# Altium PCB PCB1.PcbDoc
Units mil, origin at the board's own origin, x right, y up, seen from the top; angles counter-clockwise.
Board outline 1411.86 x 1442.8 mil, 4 copper layers (Top Layer, GND, Sign, Bottom Layer), stack 74.06 mil thick; 76 components, 64 nets, 335 pads, 393 vias.
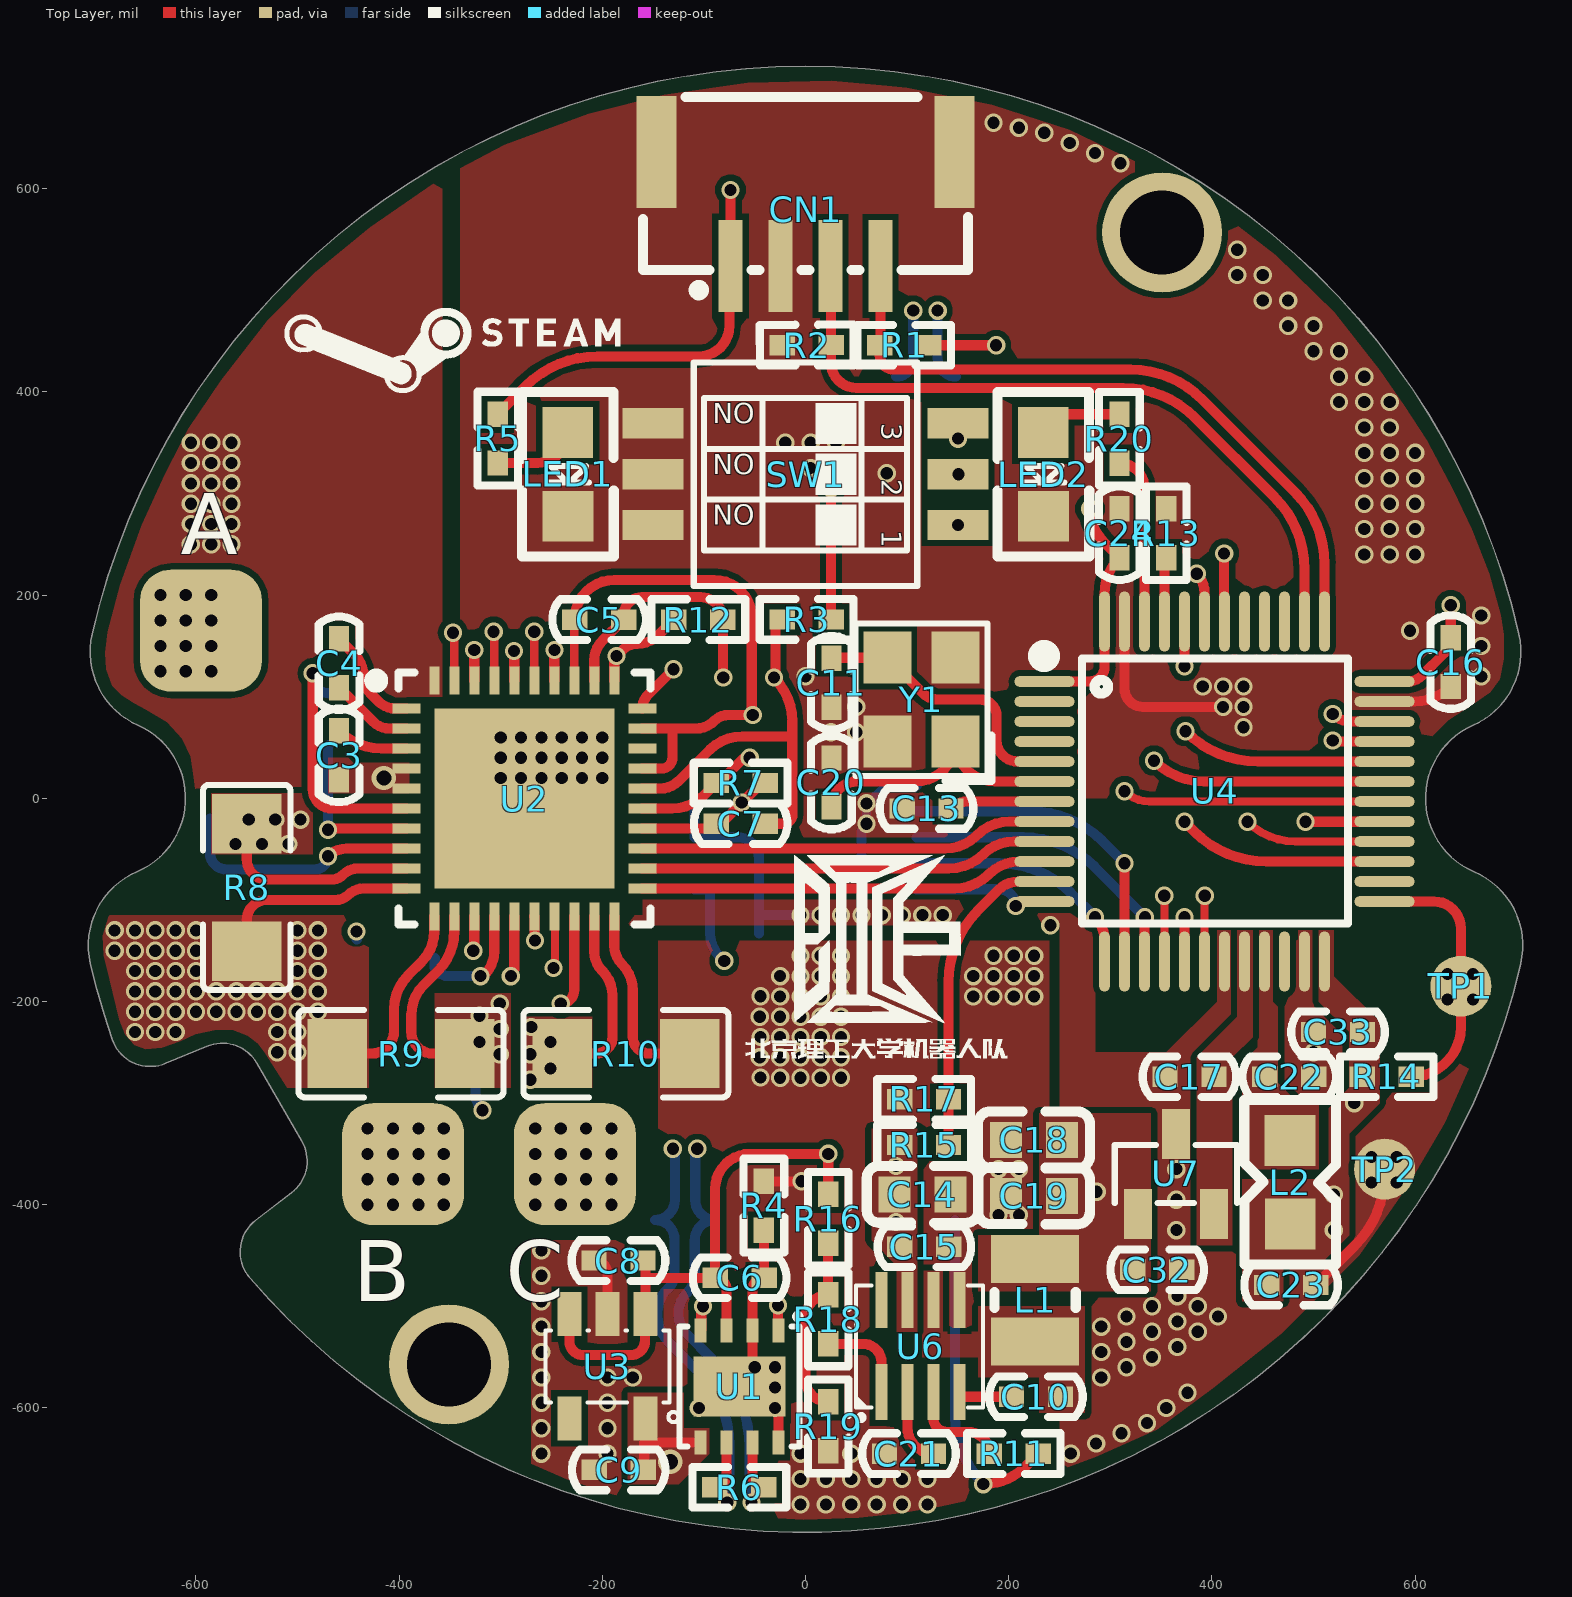
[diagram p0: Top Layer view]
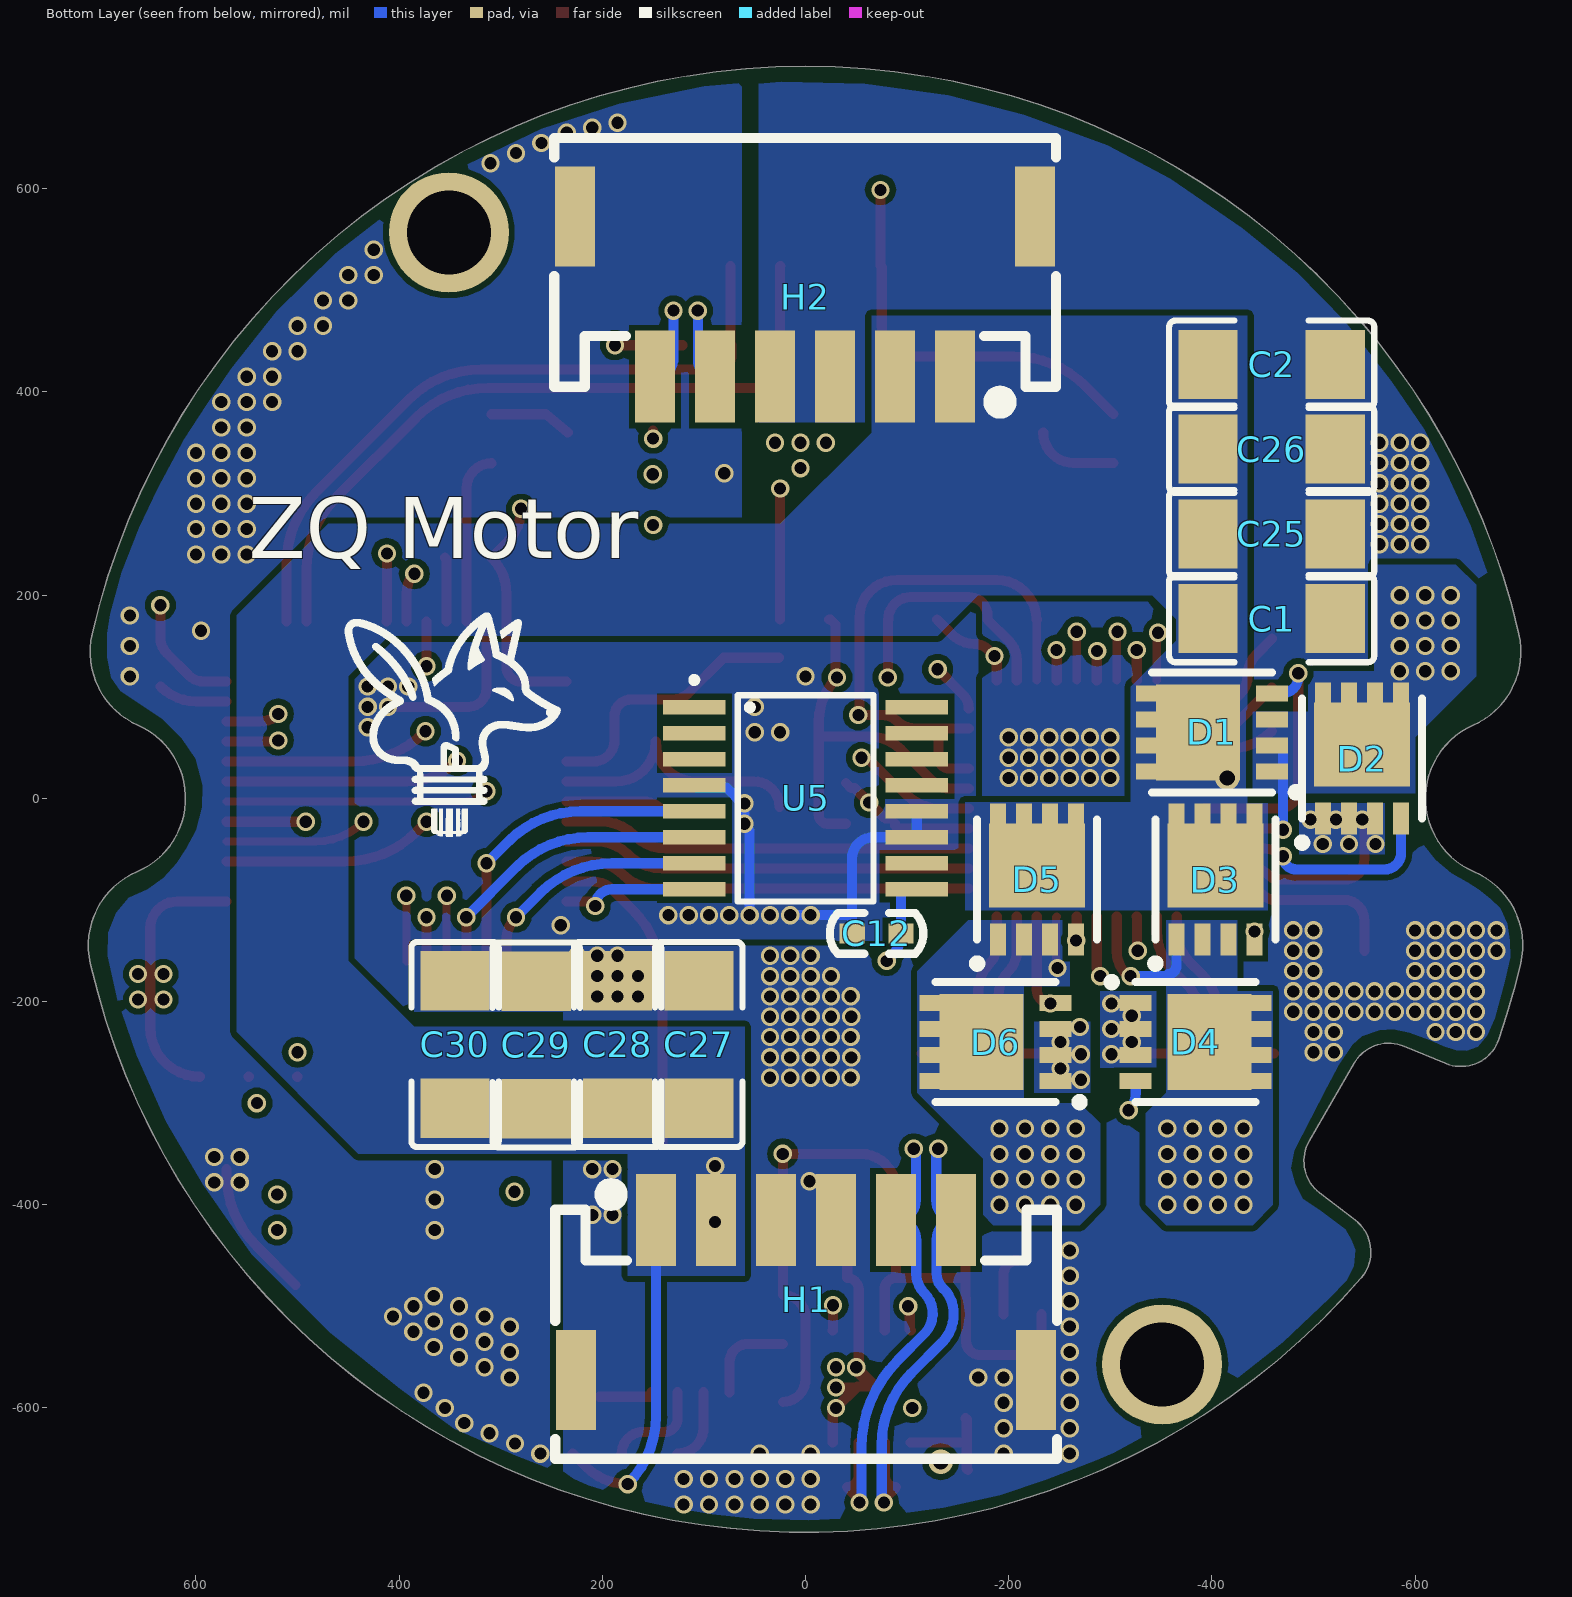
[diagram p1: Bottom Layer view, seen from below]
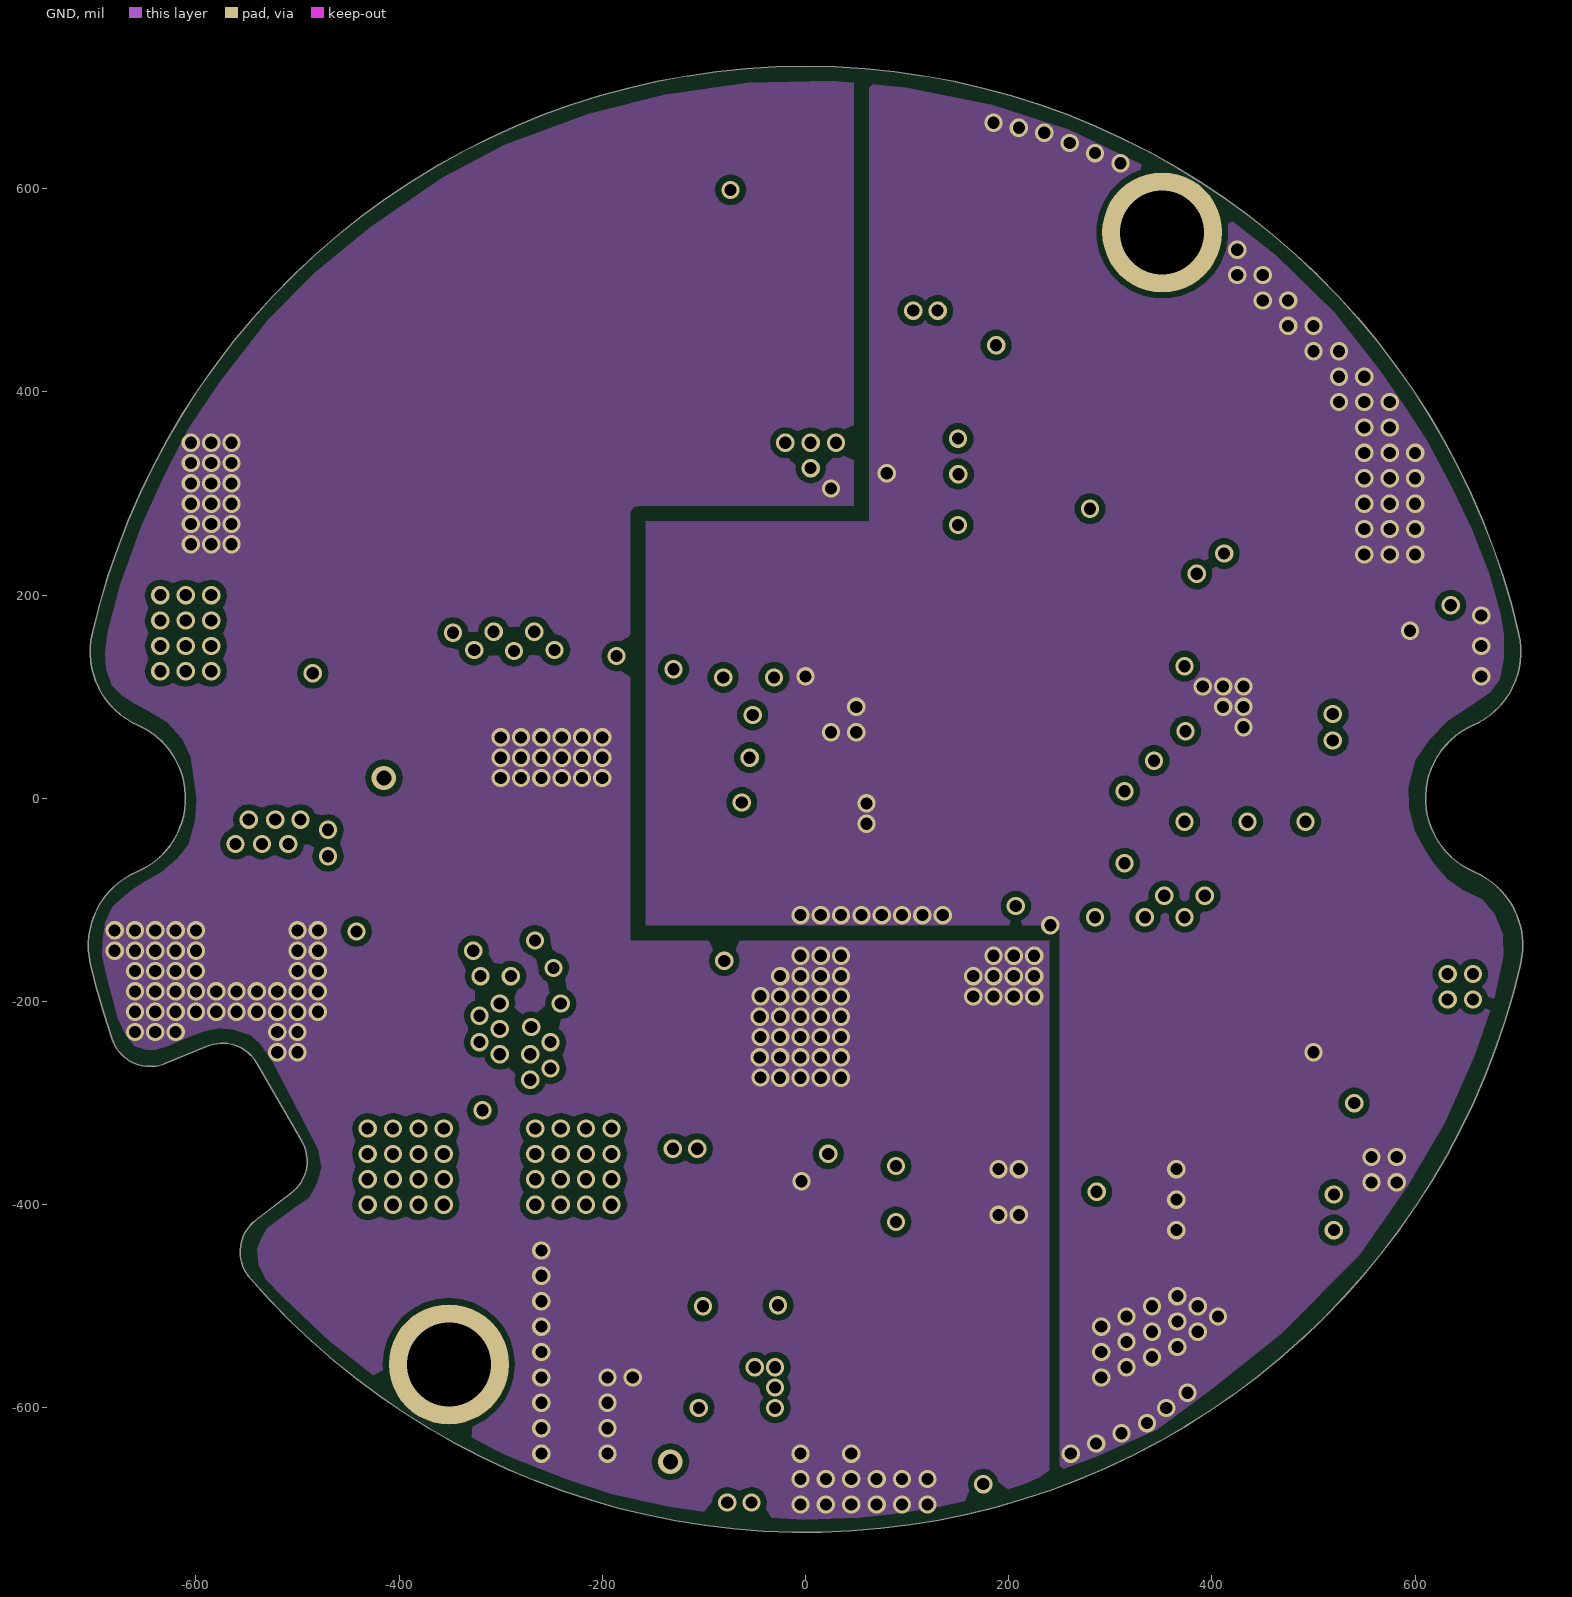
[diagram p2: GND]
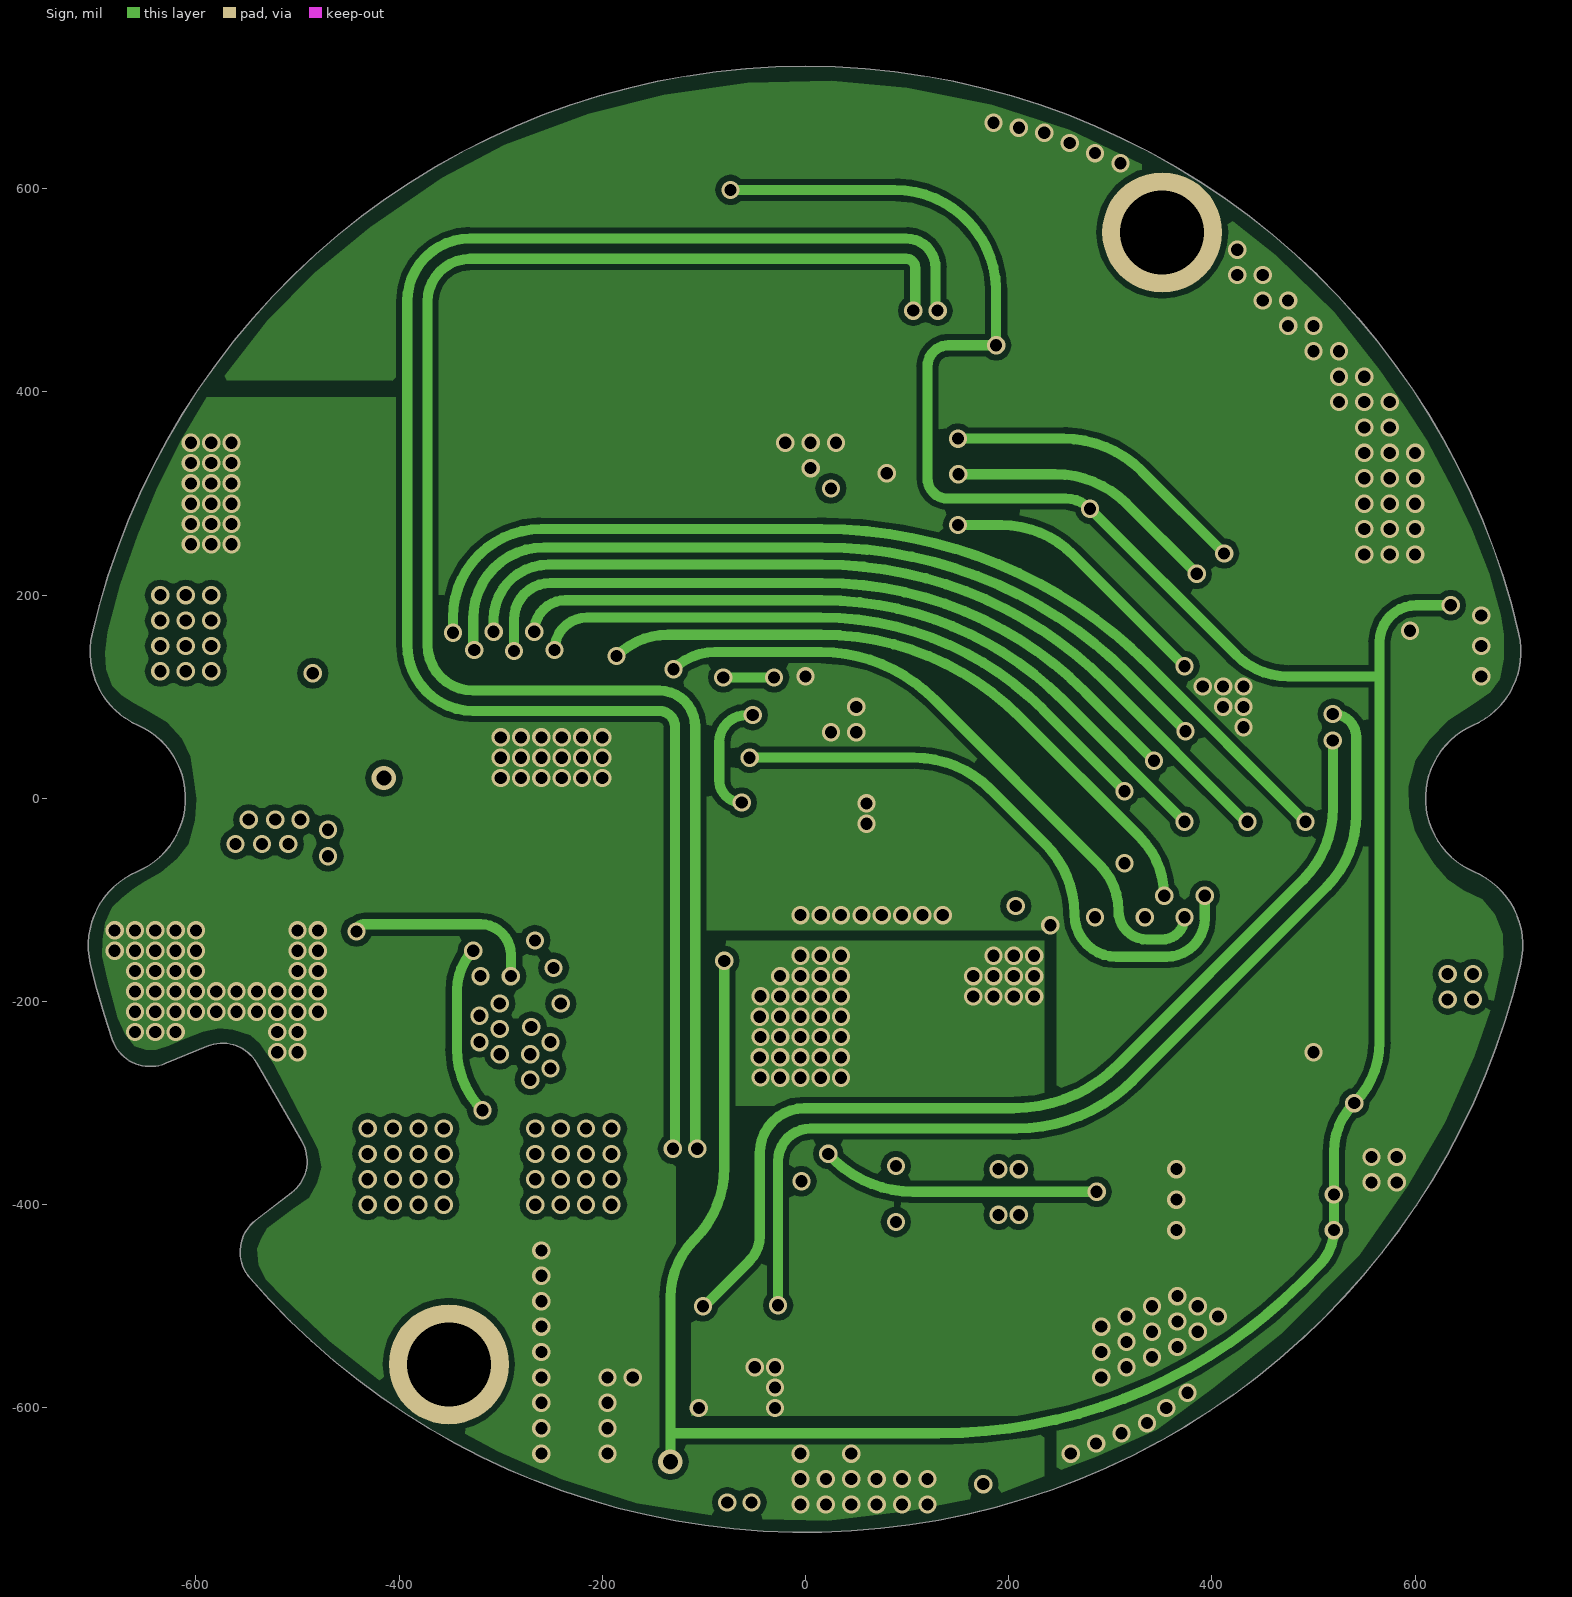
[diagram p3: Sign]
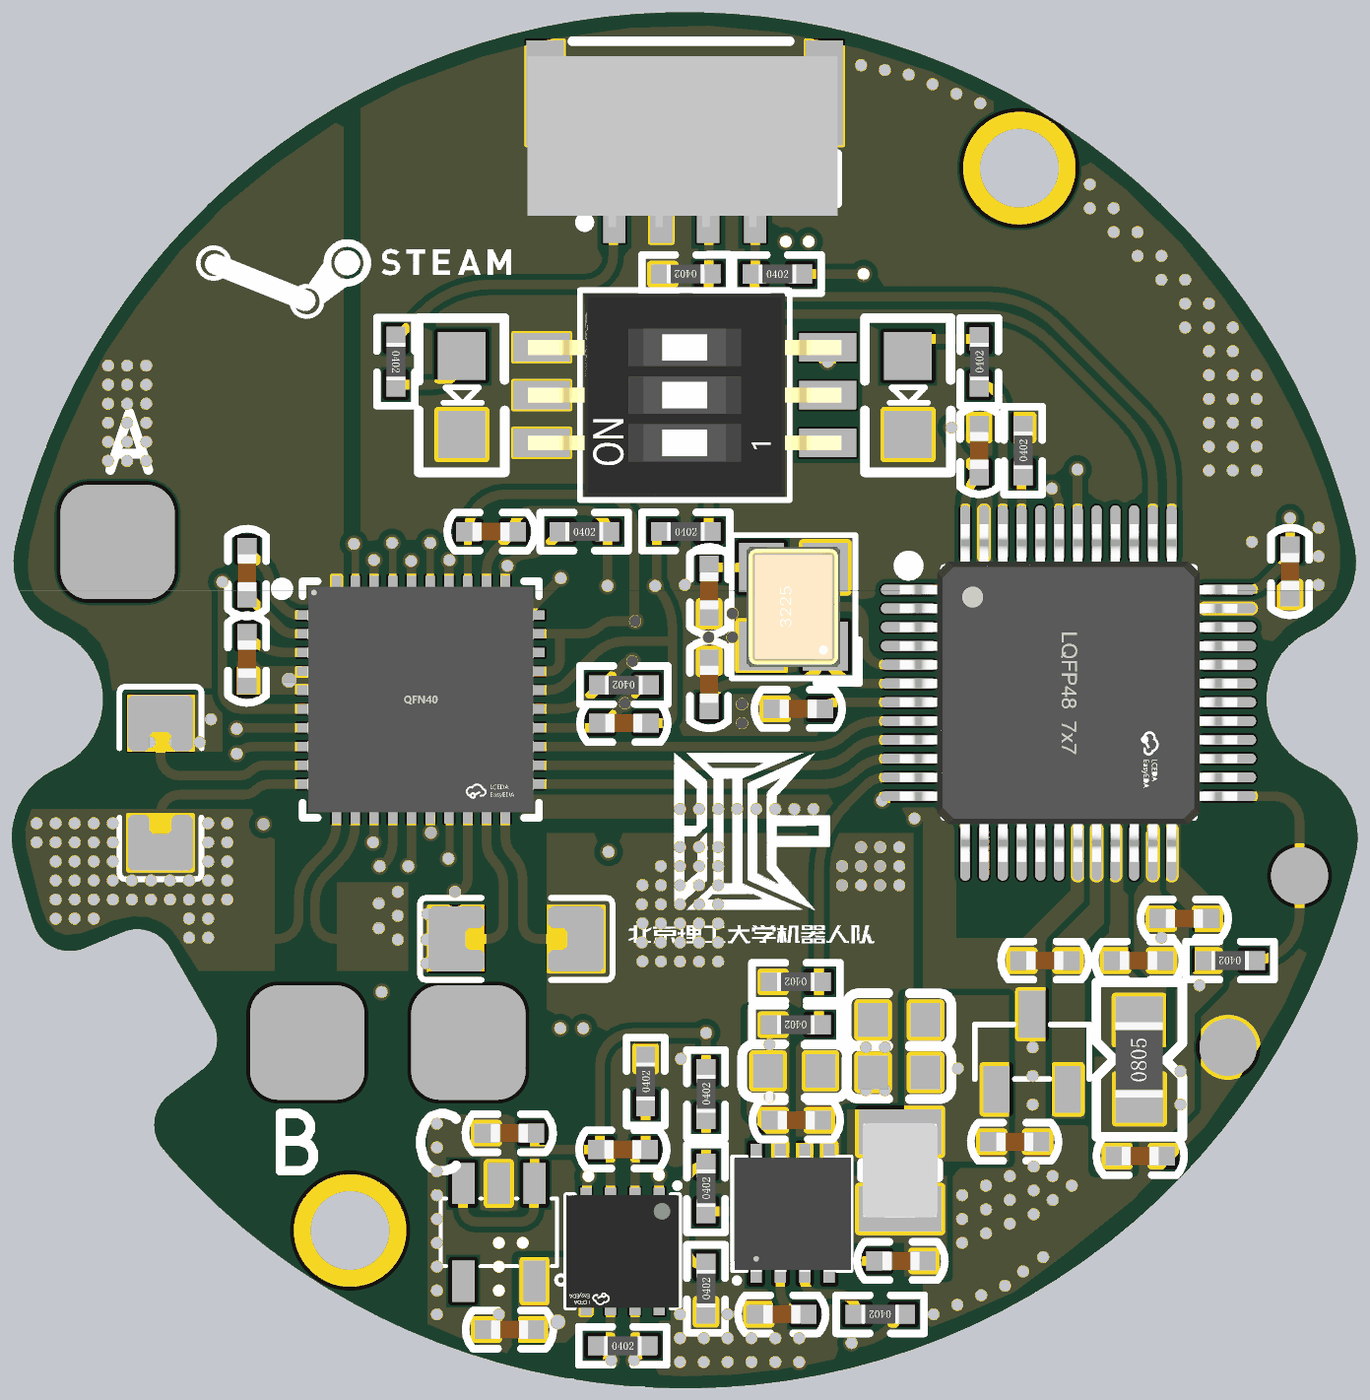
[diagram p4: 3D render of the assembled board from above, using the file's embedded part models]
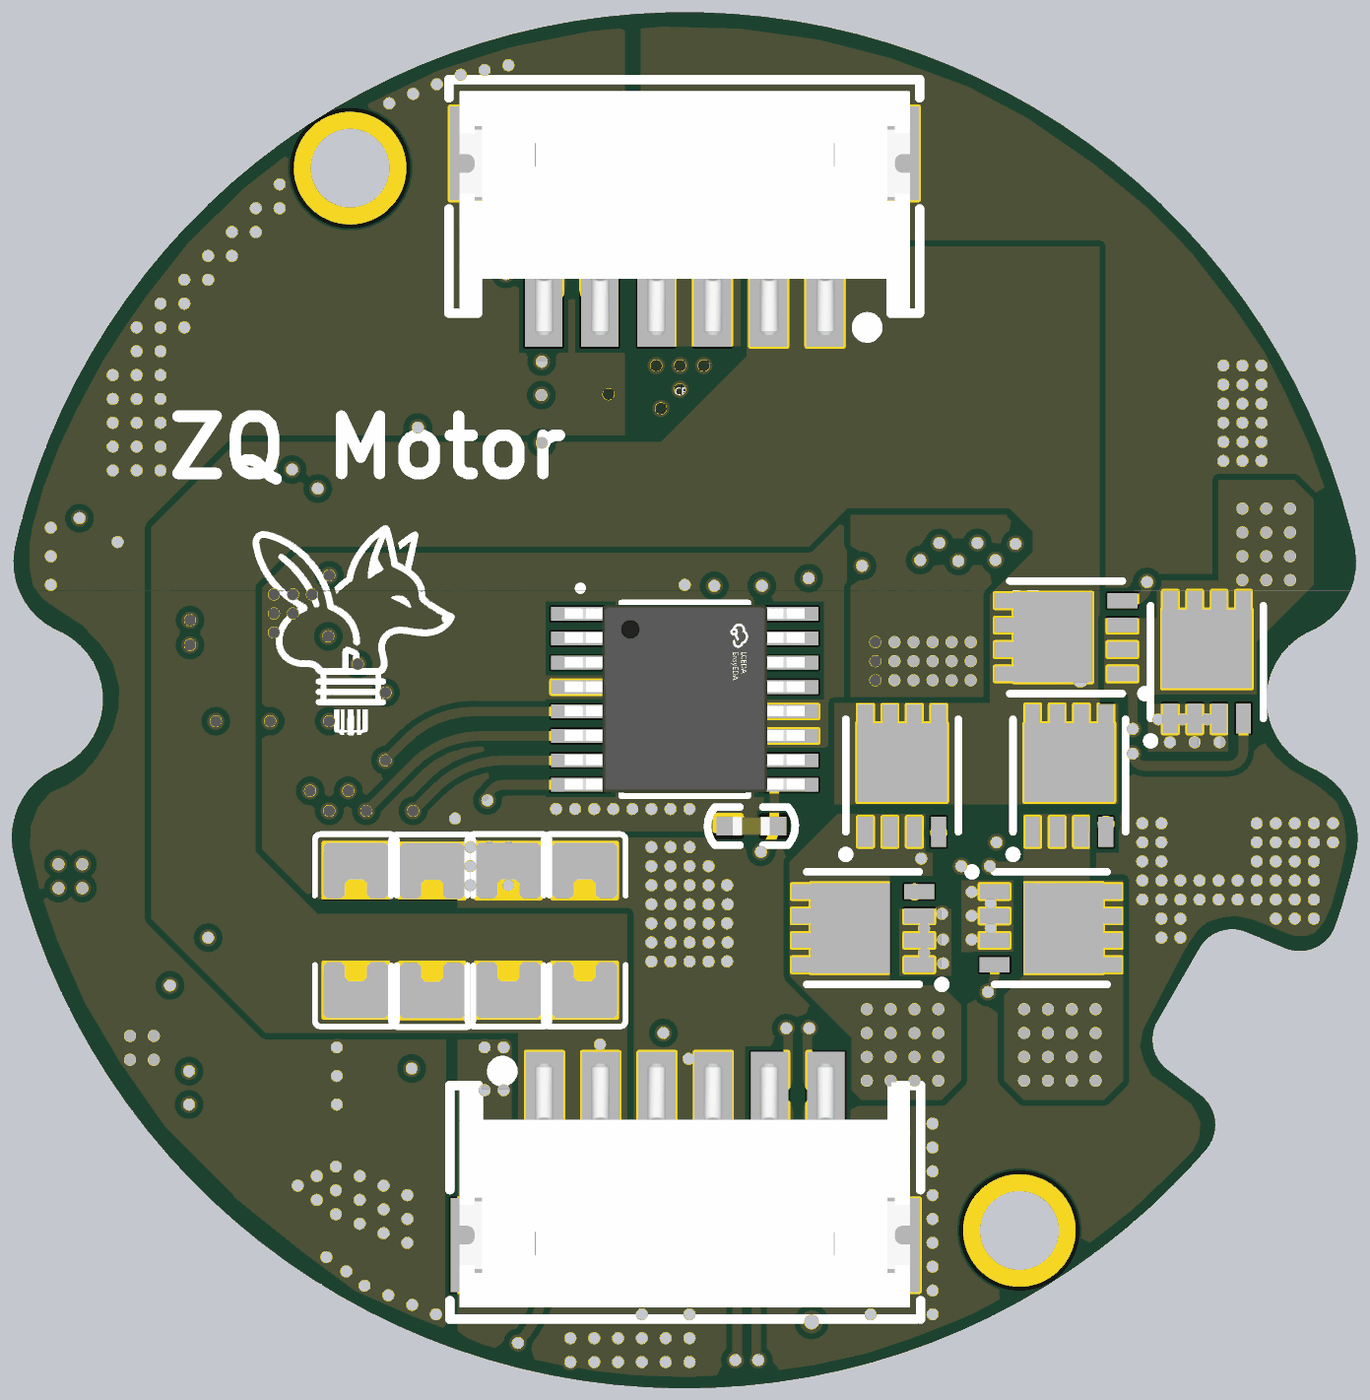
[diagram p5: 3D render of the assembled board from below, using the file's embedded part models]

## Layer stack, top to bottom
Top Solder: solder mask 0.4, Solder Resist, Dk 3.5
Top Layer: signal copper 1.4
Dielectric 2: prepreg 10.6299, PP-006, Dk 4.1
GND: signal copper 1.378
Dielectric 1: dielectric 47.244, FR-4, Dk 4.8
Sign: signal copper 1.378
Dielectric 3: prepreg 10.6299, PP-006, Dk 4.1
Bottom Layer: signal copper 1.4
Bottom Solder: solder mask 0.4, Solder Resist, Dk 3.5

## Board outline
-546.84,-472.1 cw(c-517.04,-446.38) -541.01,-415.14 -505.93,-388.23 ccw(c-529.9,-356.99) -495.81,-337.31 -540.02,-260.73 ccw(c-574.11,-280.41) -589.18,-244.04 -630.03,-260.96 cw(c-645.1,-224.58) -682.28,-237.53 cw(c0,0) -703.91,-162.57 cw(c-627.19,-144.85) -658.08,-72.43 ccw(c-688.98,0) -657.17,72.03 cw(c-625.35,144.06) -702.08,161.73 cw(c0,0) 702.08,161.73 cw(c625.35,144.06) 657.17,72.03 ccw(c688.98,0) 658.08,-72.43 cw(c627.19,-144.85) 703.91,-162.57 cw(c0,0)

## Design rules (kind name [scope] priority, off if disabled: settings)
Clearance [All] p1: gap=6 ignorepadtopadclearanceinfootprint=FALSE except(0: Arc-Hole Track-Hole SMDPad-Hole THPad-Hole Via-Hole Fill-Hole Poly-Hole Region-Hole Text-Hole)
DiffPairsRouting [All] p1: maxlimit=10 minlimit=10 mostfreqgap=10 toplayer_minwidth=8 toplayer_maxwidth=15 toplayer_prefwidth=10 midlayer1_minwidth=8 midlayer1_maxwidth=15 midlayer1_prefwidth=10 midlayer2_minwidth=8 midlayer2_maxwidth=15 midlayer2_prefwidth=10 bottomlayer_minwidth=8 bottomlayer_maxwidth=15 bottomlayer_prefwidth=10 maxuncoupledlength=500
HoleSize [All] p1: absolutevalues=TRUE maxlimit=10000 minlimit=1 maxpercent=80.000 minpercent=20.000
HoleToHoleClearance [All] p1: gap=0 allowstackedmicrovias=TRUE
MinimumSolderMaskSliver [All] p1: minsoldermaskwidth=0
PlaneClearance [All] p1: clearance=6
PlaneConnect [All] p1: planeconnectstyle=Direct reliefexpansion=20 reliefentries=4 reliefconductorwidth=10 reliefairgap=10
PolygonConnect [All] p1: connectstyle=Direct reliefconductorwidth=10 reliefentries=4 polygonreliefangle="90 Angle" airgapwidth=10
RoutingVias [All] p1: holewidth=12 width=18 viastyle="Through Hole" minholewidth=12 minwidth=18 maxholewidth=28 maxwidth=50
SilkToSilkClearance [All] p1: silktosilkclearance=0
SilkToSolderMaskClearance [IsPad] p1: minsilkscreentomaskgap=0 clearancetoexposedcopper=TRUE
SolderMaskExpansion [All] p1: expansion=4 istentingtop=FALSE
Width [All] p1: maxlimit=20 minlimit=8 preferedwidth=10
22 further rules are at their usual default settings.

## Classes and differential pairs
differential pair CAN: +CAN_P -CAN_N

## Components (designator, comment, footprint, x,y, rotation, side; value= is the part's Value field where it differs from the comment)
C1 "100uF" 1206 -1049.75,159.95 r0 bottom
C2 "100uF" 1206 -1049.75,410.11 r0 bottom
C3 "1uF" c0402 -459.14,66.35 r270 top
C4 "47nF" c0402 -459.14,156.97 r270 top
C5 "1uF" c0402 -179.05,175.88 r180 top
C6 "0.1uF" c0402 -40.8,-472 r180 top
C7 "0.1uF" c0402 -39.8,-25 r180 top
C8 "10uF" c0402 -208.2,-455 r0 top
C9 "10uF" c0402 -208,-661 r0 top
C10 "100nF" c0402 202.73,-588.97 r0 top
C11 "15pF" c0402 25.54,137.9 r270 top
C12 "100nF" C0402 -94,-133 r0 bottom
C13 "0.1uF" c0402 143.2,-10 r180 top
C14 "10uF" C0603 730.24,-301.82 r180 top
C15 "100nF" c0402 141.13,-441.45 r180 top
C16 "0.1uF" c0402 635,158.2 r270 top
C17 "0.1uF" c0402 402,-274 r180 top
C18 "10uF" C0603 -390.24,-424.25 r0 top
C19 "10uF" C0603 -390.24,-479.25 r0 top
C20 "15pF" c0402 25.54,-8.5 r90 top
C21 "100nF" c0402 77.73,-644.97 r0 top
C22 "0.1uF" c0402 500.2,-274 r180 top
C23 "0.1uF" c0402 502,-479 r180 top
C24 "0.1uF" c0402 309,236.8 r90 top
C25 "100uF" 1206 -1049.75,243.34 r0 bottom
C26 "100uF" 1206 -1049.75,326.73 r0 bottom
C27 "100uF" 1206 88.02,348.63 r270 bottom
C28 "100uF" 1206 168.02,348.63 r270 bottom
C29 "100uF" 1206 248.02,348.23 r270 bottom
C30 "100uF" 1206 328.02,348.63 r270 bottom
C32 "0.1uF" c0402 322,-464 r0 top
C33 "0.1uF" c0402 500,-230 r0 top
CN1 "卧式STLINK" CONN-SMD_4P-P1.25_GH1.25-4P 0,580 r180 top locked
D1 "NTMFS5C410NL" DFN-8_L3.0-W3.0-P0.65-BL -400,65 r90 bottom
D2 "NTMFS5C410NL" DFN-8_L3.0-W3.0-P0.65-BL -547.79,39.06 r180 bottom
D3 "NTMFS5C410NL" DFN-8_L3.0-W3.0-P0.65-BL -403.39,-80 r180 bottom
D4 "NTMFS5C410NL" DFN-8_L3.0-W3.0-P0.65-BL -384,-240 r270 bottom
D5 "NTMFS5C410NL" DFN-8_L3.0-W3.0-P0.65-BL -228,-80 r180 bottom
D6 "NTMFS5C410NL" DFN-8_L3.0-W3.0-P0.65-BL -187,-240 r90 bottom
H1 "卧式XH1.5 6PIN" CONN-SMD_6P-P1.50_ZX-ZH1.5-6PWT 0,-510 r180 bottom locked
H2 "卧式XH1.5 6PIN" CONN-SMD_6P-P1.50_ZX-ZH1.5-6PWT 0,510 r0 bottom locked
L1 "22uH" IND-SMD_L2.5-W2.0 225.93,-493.97 r270 top value=10uH
L2 "10μH" L0805 477,-419 r90 top
LED1 "LED" led0805 -234,360 r270 top
LED2 "LED" led0805 234,360 r270 top
R1 "10KΩ" R0402 73,446 r0 top
R2 "10KΩ" R0402 25.2,446.18 r180.21 top
R3 "0Ω" R0402 -23,176 r0 top
R4 "0Ω" R0402 -41,-425 r90 top
R5 "2KΩ" R0402 -303,378.2 r270 top
R6 "120Ω" R0402 -89.2,-678 r0 top
R7 "10KΩ" R0402 -39.8,15 r180 top
R8 "30mR" 1206 -566.98,-678.63 r90 top
R9 "30mR" 1206 -989.09,-234.31 r0 top
R10 "30mR" 1206 414.17,-268.28 r180 top
R11 "10KΩ" R0402 229.13,-644.97 r180 top
R12 "200KΩ" R0402 -129.55,175.88 r0 top
R13 "10KΩ" R0402 355,236.8 r90 top
R14 "2KΩ" R0402 596.2,-274 r180 top
R15 "10KΩ" R0402 140.74,-341.3 r180 top
R16 "43KΩ" R0402 22.26,-437.97 r90 top
R17 "1KΩ" R0402 140.74,-296.3 r180 top
R18 "51KΩ" R0402 22.26,-536.97 r90 top
R19 "8.2KΩ" R0402 22.26,-642.26 r90 top
R20 "2KΩ" R0402 309,329.8 r90 top
SW1 "DSHP03TSGER" SW-SMD_6P-L5.4-W5.4-P1.27-LS8.4 0,319 r90 top locked
TP1 "testpoint" testpoint 645,-185 r270 top
TP2 "testpoint" testpoint 570,-365 r0 top
U1 "SIT1057QTK/3" DFN-8_L3.0-W3.0-P0.65-BL-EP -65.1,-578.97 r180 top
U2 "DRV8323HRTAR" QFN-40_L6.0-W6.0-P0.50-BL-EP4.5 -276.83,-0.24 r270 top
U3 "XC6201P332MR-HXY" SOT-23-5_L3.0-W1.7-P0.95-LS2.8-BR -195,-559 r90 top
U4 "STM32G474CET6_1" LQFP-48_L7.0-W7.0-P0.50-LS9.0-BL 402.54,6.7 r270 top
U5 "MT6825GT-STD" TSSOP-16_L5.0-W4.4-P0.65-LS6.4-BL-1 0,0 r270 bottom locked
U6 "MP9943" "QFN-8 3x3" 74.75,-584.52 r90 top
U7 "REF3133AIDBZR" SOT-23-3_L2.9-W1.3-P1.90-LS2.4-BR 519.31,-150.65 r270 top
Y1 "3225贴片晶振" OSC-3225-4P 114,97.04 r90 top value=16M

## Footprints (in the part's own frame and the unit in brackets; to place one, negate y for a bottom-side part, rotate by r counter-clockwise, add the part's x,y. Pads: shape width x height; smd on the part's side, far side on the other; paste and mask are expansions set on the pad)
1206 [mm]
  rect 1.485x1.728 smd paste-100 mask+0.051: 1(13.417,-0.431) 2(16.602,-0.431)
  silkscreen extent 12.45,-1.52 17.57,0.66, body extent 13.41,-1.24 16.61,0.38, height 1.11
c0402 [mil]
  rect 25x20 smd: 1(0,0) 2(48.2,0)
  silkscreen extent -22,-20 70,20, body extent 5,-10 44,10, height 20
C0402 [mil]
  rect 25x20 smd: 1(0,0) 2(48.2,0)
  silkscreen extent -22,-20 70,20, body extent 5,-10 44,10, height 20
C0603 [mm]
  rect 0.8x0.9 smd: 1(14.93,2.234) 2(16.33,2.234)
  silkscreen extent 14.22,1.52 17.02,2.95, body extent 14.82,1.84 16.42,2.64, height 0.78
CONN-SMD_4P-P1.25_GH1.25-4P [mm]
  rect 0.6x2.3 smd mask+0.051: 1(1.875,1.425) 2(0.625,1.425) 3(-0.625,1.425) 4(-1.875,1.425)
  rect 1x2.8 smd mask+0.051: 5(-3.725,-1.425) 6(3.725,-1.425)
  silkscreen extent -4.06,-2.8 4.06,2.16, body extent -4.07,-2.4 4.19,2.15, height 4.13
CONN-SMD_6P-P1.50_ZX-ZH1.5-6PWT [mm]
  rect 1x2.3 smd paste+0 mask+0.05: 1(-3.738,2.413) 2(-2.238,2.413) 3(-0.738,2.413) 4(0.762,2.413) 5(2.262,2.413) 6(3.762,2.413)
  rect 1x2.5 smd paste+0 mask+0.05: 7(5.762,-1.587) 8(-5.738,-1.587)
  silkscreen extent -6.26,-3.56 6.28,3.46, body extent -6,-3.25 6.01,3.25, height 3.78
DFN-8_L3.0-W3.0-P0.65-BL [mm]
  rect 0.4x0.8 smd paste-100 mask+0.051: D(-0.975,1.5) D(-0.325,1.5) D(0.325,1.5) D(0.975,1.5) G(0.975,-1.5) S(-0.975,-1.5) S(-0.325,-1.5) S(0.325,-1.5)
  rect 2.4x2.1 smd paste-100 mask+0.051: D(0,0.35)
  silkscreen extent -1.6,-2.2 1.5,1.5, body extent -1.55,-1.6 1.55,1.6, height 0.8
DFN-8_L3.0-W3.0-P0.65-BL-EP [mm]
  rect 0.3x0.6 smd paste+0 mask+0.05: 1(-0.975,-1.4) 2(-0.325,-1.4) 3(0.325,-1.4) 4(0.975,-1.4) 5(0.975,1.4) 6(0.325,1.4) 7(-0.325,1.4) 8(-0.975,1.4)
  rect 2.3x1.5 smd paste+0 mask+0.05: 9(0,0)
  silkscreen extent -1.51,-1.8 1.5,1.5, body extent -1.5,-1.5 1.5,1.5, height 1.01
IND-SMD_L2.5-W2.0 [mm]
  rect 1.2x2.2 smd: 1(1.028,0) 2(-1.028,0)
  silkscreen extent -0.2,-1.02 0.2,1.02, body extent -1.26,-1 1.26,1, height 1.2
L0805 [mil]
  rect 50x50 smd: 1(0,0) 2(82.3,0.2)
  silkscreen extent -40,-45 122,45, body extent 1,-24 80,25, height 22
led0805 [mil] "1/8W"
  rect 50x50 smd: 1(0,0) 2(82.3,0.2)
  silkscreen extent -40,-45 122,45, body extent 2,-25 80,25, height 20
LQFP-48_L7.0-W7.0-P0.50-LS9.0-BL [mm]
  oval 0.27x1.5 smd paste+0 mask+0.05: 1(-2.75,-4.25) 2(-2.25,-4.25) 3(-1.75,-4.25) 4(-1.25,-4.25) 5(-0.75,-4.25) 6(-0.25,-4.25) 7(0.25,-4.25) 8(0.75,-4.25) 9(1.25,-4.25) 10(1.75,-4.25) 11(2.25,-4.25) 12(2.75,-4.25) 25(2.75,4.25) 26(2.25,4.25) 27(1.75,4.25) 28(1.25,4.25) 29(0.75,4.25) 30(0.25,4.25) 31(-0.25,4.25) 32(-0.75,4.25) 33(-1.25,4.25) 34(-1.75,4.25) 35(-2.25,4.25) 36(-2.75,4.25)
  oval 1.5x0.27 smd paste+0 mask+0.05: 13(4.25,-2.75) 14(4.25,-2.25) 15(4.25,-1.75) 16(4.25,-1.25) 17(4.25,-0.75) 18(4.25,-0.25) 19(4.25,0.25) 20(4.25,0.75) 21(4.25,1.25) 22(4.25,1.75) 23(4.25,2.25) 24(4.25,2.75) 37(-4.25,2.75) 38(-4.25,2.25) 39(-4.25,1.75) 40(-4.25,1.25) 41(-4.25,0.75) 42(-4.25,0.25) 43(-4.25,-0.25) 44(-4.25,-0.75) 45(-4.25,-1.25) 46(-4.25,-1.75) 47(-4.25,-2.25) 48(-4.25,-2.75)
  silkscreen extent -3.59,-4.46 3.3,3.34, body extent -4.5,-4.5 4.5,4.5, height 1.45
OSC-3225-4P [mm] "3.2*2.5*0.7mm(长宽高)                             淘宝ID:黄晶宝石"
  rect 1.3x1.2 smd: 1(-1.05,-0.85) 2(1.05,-0.85) 3(1.05,0.85) 4(-1.05,0.85)
  silkscreen extent -2.03,-1.75 1.91,1.65, body extent -1.6,-1.25 1.6,1.25, height 0.7
"QFN-8 3x3" [mm]
  rect 1.4x0.3 smd: 1(0,0) 2(0,-0.65) 3(0,-1.3) 4(0,-1.95) 5(2.3,-1.95) 6(2.3,-1.3) 7(2.3,-0.65) 8(2.3,0)
  silkscreen extent -0.64,-2.54 2.67,0.64, body extent -0.41,-2.53 2.69,0.57, height 0.94
QFN-40_L6.0-W6.0-P0.50-BL-EP4.5 [mm]
  rect 0.25x0.7 smd paste-100 mask+0.051: 1(-2.25,-2.95) 2(-1.75,-2.95) 3(-1.25,-2.95) 4(-0.75,-2.95) 5(-0.25,-2.95) 6(0.25,-2.95) 7(0.75,-2.95) 8(1.25,-2.95) 9(1.75,-2.95) 10(2.25,-2.95) 21(2.25,2.95) 22(1.75,2.95) 23(1.25,2.95) 24(0.75,2.95) 25(0.25,2.95) 26(-0.25,2.95) 27(-0.75,2.95) 28(-1.25,2.95) 29(-1.75,2.95) 30(-2.25,2.95)
  rect 0.7x0.25 smd paste-100 mask+0.051: 11(2.95,-2.25) 12(2.95,-1.75) 13(2.95,-1.25) 14(2.95,-0.75) 15(2.95,-0.25) 16(2.95,0.25) 17(2.95,0.75) 18(2.95,1.25) 19(2.95,1.75) 20(2.95,2.25) 31(-2.95,2.25) 32(-2.95,1.75) 33(-2.95,1.25) 34(-2.95,0.75) 35(-2.95,0.25) 36(-2.95,-0.25) 37(-2.95,-0.75) 38(-2.95,-1.25) 39(-2.95,-1.75) 40(-2.95,-2.25)
  rect 4.5x4.5 smd paste-100 mask+0.051: 41(0,0)
  silkscreen extent -3.15,-3.85 3.15,3.15, body extent -3.01,-3.01 3.01,3.01, height 0.83
R0402 [mil] "1/16W"
  rect 25x20 smd: 1(0,0) 2(48.2,0)
  silkscreen extent -22,-20 70,20, body extent 5,-10 44,10, height 14
SOT-23-3_L2.9-W1.3-P1.90-LS2.4-BR [mm]
  rect 1.25x0.7 smd: 1(6.562,-4.885) 2(6.562,-2.985) 3(4.562,-3.935)
  silkscreen extent 4.84,-5.46 6.29,-2.41, body extent 4.19,-5.39 6.99,-2.49, height 1.3
SOT-23-5_L3.0-W1.7-P0.95-LS2.8-BR [mm]
  rect 1.1x0.6 smd: 1(1.3,-0.95) 2(1.3,0) 3(1.3,0.95) 4(-1.3,0.95) 5(-1.3,-0.95)
  silkscreen extent -1.4,-1.78 0.9,1.55, body extent -1.5,-1.5 1.5,1.5, height 1.3
SW-SMD_6P-L5.4-W5.4-P1.27-LS8.4 [mil]
  rect 30x60 smd paste+0 mask+2: 1(-50,-150) 2(0,-150) 3(50,-150) 4(50,150) 5(0,150) 6(-50,150)
  silkscreen extent -110,-110 110,110, body extent -106,-164 106,164, height 91
testpoint [mil]
  round 60 smd: 1(0,0)
TSSOP-16_L5.0-W4.4-P0.65-LS6.4-BL-1 [mm]
  rect 0.364x1.56 smd paste+0 mask+0.051: 1(-2.275,-2.78) 2(-1.625,-2.78) 3(-0.975,-2.78) 4(-0.325,-2.78) 5(0.325,-2.78) 6(0.975,-2.78) 7(1.625,-2.78) 8(2.275,-2.78) 9(2.275,2.78) 10(1.625,2.78) 11(0.975,2.78) 12(0.325,2.78) 13(-0.325,2.78) 14(-0.975,2.78) 15(-1.625,2.78) 16(-2.275,2.78)
  silkscreen extent -3.03,-2.85 2.58,1.7, body extent -2.51,-3.2 2.49,3.2, height 1.09

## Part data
C1 C2 C14 C18 C19 C25 C26 C27 C28 C29 C30: library part 1210贴片电容, "1210贴片电容"
C3 C4 C5 C6 C7 C8 C9 C10 C11 C12 C13 C15 C16 C17 C20 C21 C22 C23 C24 C32 C33: library part 0402贴片电容, "贴片电容0402"
D1 D2 D3 D4 D5 D6: "N沟道MOS管"
L1: library part 0530屏蔽电感, "一体成型屏蔽电感，0530封装，额定电流3A", DC Resistance (DCR)=125mΩ, JLCPCB Part Class="Extended Part", LCSC Part Name="10uH ±20% 3.5A", Manufacturer=XR(祥如), Manufacturer Part=XR0530-100M, Rated Current=3.2A, Saturation Current (Isat)=3.5A, Tolerance=±20%
L2: library part 0805贴片电感, "0805贴片电感"
LED1 LED2: library part 0805贴片LED, "0805贴片LED"
R1 R2 R3 R4 R5 R6 R7 R11 R12 R13 R14 R15 R16 R17 R18 R19 R20: library part 0402贴片电阻, "0402贴片电阻"
R8 R9 R10: library part 2512检流电阻, "2512检流电阻"
U2: JLCPCB Part Class="Extended Part", LCSC Part Name="5mA 无刷直流BLDC电机驱动芯片 60V", Manufacturer=TI(德州仪器)
U3: "3.3V LDO", JLCPCB Part Class="Extended Part", Manufacturer="HXY MOSFET(华轩阳电子)", MAX Output Current=300mA, Maximum Input Voltage=12V, Output Voltage=3.3V
U5: "18位绝对角编码器"

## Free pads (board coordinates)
  round 118.11 hole 82.68: 4(-351.07,-557.07) 6(351.07,557.07)
  rrect50% 120x120 smd: 14(-595,165) 14(-396,-360) 14(-227,-360)

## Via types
v1: diameter 18, hole 12, Top Layer to Bottom Layer, tented both sides, 391 vias
v2: diameter 24, hole 15, Top Layer to Bottom Layer, tented both sides, 2 vias

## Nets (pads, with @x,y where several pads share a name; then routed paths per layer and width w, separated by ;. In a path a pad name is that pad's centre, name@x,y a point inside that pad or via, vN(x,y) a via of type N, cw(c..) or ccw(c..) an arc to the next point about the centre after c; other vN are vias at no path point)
3V3: C9.2 C12.1 C16.1 C23.2 C24.1 C33.2 CN1.1 L2.1 R1.2 R5.1 R14.2 U1.5 U3.5 U4.1 U4.24 U4.36 U4.48 U5.9 | length 4014.5
  Top Layer w10: R5.1 -275.49,405.71 cw(c-204.78,335) -204.78,435 -105,435 ccw(c-105,465) -75,465 -75,522.72 cw(c-73.82,522.72) CN1.1 v1(-73.82,598.82) ; C9.2 -158.7,-659.9 -158.7,-634 -158.61,-634.09 ; U3.5 -158.61,-611.19 -158.61,-634.09 ; U1.5 -158.61,-634.09 ; R1.2 v1(187.59,446) ; U4.1 279.97,114.97 ccw(c279.97,129.27) 294.27,129.27 U4.48 294.27,201.11 cw(c344.56,201.24) 304,230.97 C24.1 293.58,252.22 cw(c326.35,285) 285.86,262.44 cw(c326.35,285) v1(280,285) ; R14.2 R14.2@548.2,-273.8 ; U4.36 592.45,114.97 ccw(c592.45,135.55) 607,121 ; 607,121 628.49,142.49 ccw(c612.79,158.2) C16.1 v1(635,190)
  Sign w10: v2(-133,-653) -133,-625 ; v1(-80,-160) -80,-363.58 cw(c-180,-363.58) -109.29,-434.29 ccw(c-52.05,-491.53) -133,-491.53 -133,-625 ; v1(-73.82,598.82) 87.59,598.82 cw(c87.59,498.75) 187.59,502.42 v1(187.59,446) 141,446 ccw(c141,425) 120,425 120,315 ccw(c140,315) 140,295 255.86,295 cw(c255.86,260.86) v1@280,285 ; v1(280,285) 423.79,141.21 ccw(c475,192.43) 475,120 565,120 ; 565,84.16 565,-239.64 cw(c479.64,-239.64) 540.04,-299.96 cw(c479.64,-239.64) v1(540,-300) ccw(c588.28,-348.28) 520,-348.28 v1(520,-390) v1(520,-425) cw(c471.72,-425) 505.86,-459.14 487.82,-477.18 cw(c131.01,-120.44) 130.94,-625 -133,-625 ; 565,84.2 565,120 ; v1(635,190) 601.42,190 ccw(c601.42,153.58) 565,153.58 565,120
  Bottom Layer w10: U5.9 -96.17,-89.57 -94,-91.73 C12.1 ccw(c-62.62,-133) -84.81,-155.19 v1(-80,-160)
5V: C6.2 C8.2 C18.2 C19.2 C32.1 L1.2 R16.2 U1.3 U3.1 U3.3 U7.1 | length 857.7
  Top Layer w10: U3.3 -232.4,-534.6 ccw(c-219,-534.6) -219,-548 -172,-548 ccw(c-172,-534) -158,-534 -158,-492 -157.6,-492 -157.6,-472 ; C8.2 cw(c-160,-457.4) -157.6,-457.4 -157.6,-472 ; U1.3 -77.89,-483.11 ccw(c-89,-483.11) C6.2 ; R16.2 22.34,-389.7 22.34,-350.02 v1(22.42,-349.94) -54.41,-349.94 ccw(c-54.41,-384.53) -89,-384.53 C6.2 ; -157.6,-472 C6.2
  Sign w10: v1(22.42,-349.94) 22.49,-350.02 ccw(c105.93,-274.97) 106.08,-387.2 v1(286.52,-387.2)
ADC1_NTC: R14.1 TP1.1 U4.25 | length 264.1
  Top Layer w10: U4.25 618.57,-101.57 cw(c618.57,-128) 645,-128 TP1.1 645,-225.2 cw(c596.2,-225.2) R14.1
  other v1: 632,-198 657,-198 632,-173 657,-173
ADC1_VCC: R15.1 R17.1 U4.11 | length 314.8
  Top Layer w10: R15.1 R17.1 140.74,-180.68 cw(c240.74,-180.68) 170.03,-109.97 190,-90 cw(c209.61,-109.61) 209.61,-81.88 U4.11
AGND: C5.1 C7.1 R3.1 R12.2 U2.26 U2.32 | length 701.5
  Top Layer w10: U2.32 -207.93,135.86 cw(c-180.86,135.86) -200,155 -179.12,175.88 C5.1 -179.05,179.95 cw(c-161,179.95) -161,198 -103.47,198 cw(c-103.47,175.88) R12.2 -81.18,175.7 -81.18,119.18 v1(-81,119) ; U2.26 -143,9.6 ccw(c-143,35.18) -124.92,17.08 -94.48,47.52 cw(c-62,15.13) -62,61 -13,61 ; C7.1 -21.63,-25 ccw(c-21.63,-16.37) -13,-16.37 -13,61 ; R3.1 -24.47,176 -29.47,171 -29.47,120.53 v1(-31,119) cw(c-74.46,75.54) -13,75.54 -13,61
  Sign w10: v1(-81,119) v1(-31,119)
CAN_N: H1.6 H2.6 R6.1 U1.6 | length 2225.1
  Top Layer w10: U1.6 -77.89,-666.69 cw(c-89.2,-666.69) R6.1 -79.15,-688.05 cw(c-84.1,-693) v1(-77.1,-693)
  Sign w10: v1@-130,-345 v1(-130.58,-345) ccw(c-130.58,-343) -128.58,-343 -128.58,70.58 ccw(c-144,70.58) -144,86 -327,86 cw(c-327,151) -392,151 -392,489 cw(c-330,489) -330,551 99,551 cw(c99,522) 128,522 128,482 ccw(c130,482) v1(130,480)
  Bottom Layer w10: v1(-130.58,-345) cw(c-130.58,-347) -128.58,-347 -128.58,-395.47 cw(c-148.11,-395.47) H1.6 cw(c-148.11,-434.11) -129,-434.11 -129,-468 cw(c-148.31,-468) -134.66,-481.66 ccw(c-113.24,-505.9) -145.57,-504.91 ccw(c-107.33,-508.37) -134.48,-535.52 -104.29,-565.71 cw(c-175,-636.42) -75,-636.42 -75,-687.93 cw(c-82.17,-687.93) v1(-77.1,-693) ; v1(-77.1,-693) v1@-77.1,-692.77 ; v1(130,480) 130,433.11 ccw(c148.11,433.11) H2.6
CAN_P: H1.5 H2.5 R6.2 U1.7 | length 2165.5
  Top Layer w10: v1(-53.1,-693) cw(c-46.1,-693) -51.05,-688.05 R6.2 cw(c-41,-666.7) -52.3,-666.7 U1.7
  Sign w10: v1@-110,-341.58 ccw(c-106.58,-341.58) v1(-106.58,-345) cw(c-106.58,-343) -108.58,-343 -108.58,70.58 ccw(c-144,70.58) -144,106 -327,106 cw(c-327,151) -372,151 -372,489 cw(c-330,489) -330,531 99,531 cw(c99,522) 108,522 108,482 cw(c106,482) v1(106,480)
  Bottom Layer w10: v1(-106.58,-345) ccw(c-106.58,-347) -108.58,-347 -108.58,-395.47 ccw(c-89.05,-395.47) H1.5 ccw(c-89.05,-434.95) -109,-434.95 -109,-468 cw(c-135.56,-468) -116.77,-486.77 ccw(c-96.51,-507.05) -118.16,-525.84 -90.86,-553.14 cw(c-177.42,-639.71) -55,-639.71 -55,-688.41 ccw(c-48.51,-688.41) v1(-53.1,-693) ; H2.5 ccw(c89.06,431.95) 106,431.95 v1(106,480)
DGND: C6.1 C11.2 C12.2 C13.2 C16.2 C17.2 C20.2 C22.1 C23.1 C24.2 C32.2 C33.1 CN1.2 CN1.5 CN1.6 H2.7 LED1.2 LED2.2 R2.2 R4.1 R13.2 SW1.4 SW1.5 SW1.6 TP2.1 U1.2 U1.8 U1.9 U4.19 U4.23 U4.35 U4.47 U5.4 U5.11 U5.12 U7.3 Y1.2 Y1.4 | length 1076.9
  Top Layer w10: v1(-50,-560) -65.1,-575.1 U1.9 ; R4.1 C6.1@-41,-472 ; C6.1 C6.1@-41,-472 ; U1.9@-32.61,-602.61 -27.61,-602.61 -26.71,-603.5 U1.8 ; v1(-30,-600) U1.9@-50,-580 ; v1(-30,-580) U1.9@-50,-580 ; U4.47 313.96,108.04 ccw(c332,108.04) 332,90 v1(411,90) ; C22.1@500,-273.8 C22.1 ; C23.1 540.71,-440.29 ccw(c470,-369.58) 570,-369.58 TP2.1 ; U4.35 599.46,95.28 ccw(c599.46,145.54) C16.2 ; U1.9 -51.03,-578.97 U1.9@-50,-580 ; U1.9 -52.3,-566.18 -52.3,-483.5 cw(c-40.8,-483.5) C6.1@-41,-472
  Bottom Layer w10: U5.12 U5.11 -66.61,-38.39 cw(c-66.61,-59.2) -45.8,-59.2 -45.8,-115 ; C12.2 -45.8,-115 ; v1(15,-115) v1(-5,-115) -45.8,-115 ; v1(55,-115) 55,-32.16 60,-27.16 v1(60,-5) 62.16,-5 77.79,10.63 107.28,10.63 U5.4
  other v1: 261,-645 286,-635 311,-625 336,-615 -105,-600 355,-600 376,-585 291,-570 -30,-560 316,-560 341,-550 291,-545 366,-540 316,-535 341,-525 386,-525 291,-520 366,-515 316,-510 406,-510 341,-500 386,-500 366,-490 365,-425 365,-395 557,-378 582,-378 365,-365 557,-353 582,-353 500,-250 241,-125 35,-115 75,-115 95,-115 115,-115 135,-115 60,-25 25,65 50,65 431,70 50,90 431,90 391,110 411,110 431,110 0,120 665,120 665,150 595,165 665,180 550,240 575,240 600,240 550,265 575,265 600,265 550,290 575,290 600,290 550,315 575,315 600,315 80,320 5,325 550,340 575,340 600,340 -20,350 5,350 30,350 550,365 575,365 525,390 550,390 575,390 525,415 550,415 500,440 525,440 475,465 500,465 450,490 475,490 425,515 450,515 425,540 310,625 285,635 260,645 235,655 210,660 185,665
DRV8323_CAL: R12.1 U2.31 U4.16 | length 813.7
  Top Layer w8: U4.16 v1@353.33,-96.33
  Top Layer w10: U2.31 -188.25,134.57 cw(c-180.57,134.57) v1(-186,140) ; v1(-186,140) -179.66,146.34 cw(c-166,132.69) -166,152 ccw(c-166,182.35) -144.54,160.89 R12.1
  Sign w10: v1@-186,140 cw(c-135.3,89.3) -135.3,161 15.12,161 15.18,161 cw(c15.46,-115.53) 211.07,79.93 ; 211.09,79.91 328.96,-37.96 cw(c270.92,-96) v1(353,-96)
DRV8323_EN: U2.30 U4.17 | length 742.1
  Top Layer w10: U2.30 cw(c-141.43,88.34) -155.05,101.95 v1(-130,127) ; U4.17 v1(373,-117)
  Sign w10: v1@-130,127 cw(c-88.96,85.96) -88.96,144 15.07,144 cw(c15.23,-12.38) 126.08,97.92 289.13,-65.13 cw(c243.57,-110.69) 308,-110.69 ccw(c336.31,-110.69) 336.31,-139 351,-139 ccw(c351,-117) v1(373,-117)
DRV8323_HA: U2.34 U4.30 | length 925.8
  Top Layer w8: v1@314,7 ccw(c338.47,31.47) 338.47,-3.14 U4.30
  Top Layer w10: U2.34 -247.3,146 v1(-247,146)
  Sign w10: v1@-247,146 cw(c-215,146) -215,178 14.89,178 cw(c15.06,-130.88) 233.57,87.43 233.63,87.37 v1(314,7)
DRV8323_HB: U2.36 U4.31 | length 1000.1
  Top Layer w10: v1(-287,145) -286.67,145 U2.36 ; v1@343,37 ccw(c392.4,86.4) 392.4,16.54 U4.31
  Sign w10: v1(-287,145) -287,176 cw(c-251,176) -251,212 16.11,212 cw(c16.46,-153.85) 275.39,104.61 275.46,104.54 v1(343,37)
DRV8323_HC: U2.38 U4.32 | length 1063.2
  Top Layer w10: U2.38@-326.02,115.92 v1(-326,146) ; v1(374,66) 374.48,65.52 ccw(c445.19,136.23) 445.19,36.23 U4.32
  Sign w10: v1(-326,146) -327,147 -327,177.5 cw(c-257.5,177.5) -257.5,247 15.89,247 cw(c16.28,-179.64) 318.29,121.71 ; 318.31,121.69 v1(374,66)
DRV8323_LA: U2.35 U4.27 | length 990.4
  Top Layer w8: U2.35@-266.99,115.9 v1(-267,164)
  Top Layer w10: v1(373,-23) 382.91,-32.91 ccw(c453.62,37.8) 453.62,-62.2 U4.27
  Sign w10: v1(-267,164) cw(c-236,164) -236,195 15.55,195 cw(c15.8,-141.05) 253.62,96.38 ; 253.64,96.36 v1(373,-23)
DRV8323_LB: U2.37 U4.28 | length 1062.6
  Top Layer w8: v1(-307,164) -306.36,164 U2.37 ; v1(435,-23) ccw(c482.09,24.09) 482.09,-42.51 U4.28
  Sign w10: v1@-308.16,164 v1(-307,164) -307,176 cw(c-253,176) -253,230 16.01,230 cw(c16.38,-165.01) 295.84,114.16 ; 295.87,114.13 433,-23 v1(435,-23)
DRV8323_LC: U2.39 U4.29 | length 1129.1
  Top Layer w8: v1(-347,163) -345.73,161.73 U2.39
  Top Layer w10: v1(492,-23) 569.86,-23 U4.29
  Sign w10: v1(-347,163) -347,178 cw(c-260,178) -260,265 15.8,265 cw(c16.06,-188.73) 337,132 ; 337.03,131.97 v1(492,-23)
DRV8323_nF: R7.2 U2.25 U4.18 | length 783.6
  Top Layer w8: U4.18 392.7,-96.3 v1(393,-96)
  Top Layer w10: U2.25 -131.63,-10.08 ; -131.59,-10.08 ccw(c-131.59,34.59) -99.99,3.01 -93,10 R7.2 -85.5,15 -62.03,38.47 -56.53,38.47 v1(-55,40)
  Sign w10: v1(-55,40) 106.75,40 ; 106.75,40 cw(c106.75,-66.83) 182.29,8.71 235.93,-44.93 cw(c166.53,-114.34) 264.68,-114.14 cw(c166.53,-114.34) 264.68,-114.34 ccw(c306.34,-114.34) 306.34,-156 355,-156 ccw(c355,-118) 393,-118 v1(393,-96)
DRV8323_SOA: U2.23 U4.8 | length 403
  Top Layer w10: U2.23 137.18,-49.45 ccw(c137.18,-5.11) 168.5,-36.5 168.54,-36.46 cw(c201.45,-69.38) 201.45,-22.83 U4.8
DRV8323_SOB: U2.22 U4.9 | length 403
  Top Layer w10: U2.22 140.86,-69.14 ccw(c140.86,-20.86) 175,-55 cw(c205.16,-85.16) 205.16,-42.51 U4.9
DRV8323_SOC: U2.21 U4.10 | length 403
  Top Layer w10: U2.21 146.63,-88.82 ccw(c146.63,-41.63) 180,-75 cw(c210.9,-105.9) 210.9,-62.2 U4.10
DVDD: C5.2 C7.2 R7.1 U2.24 U2.27 U2.29 U2.33 | length 806.8
  Top Layer w8: U2.33 C5.2@-227.62,175.88
  Top Layer w10: C5.2@-227.62,175.88 C5.2 cw(c-188.12,175.88) -188.12,215 -90,215 cw(c-90,178) -53,178 -53,83 v1(-52,82) -76.04,82 ccw(c-76.04,62.97) -89.5,76.43 cw(c-108.25,95.18) -108.25,68.66 -131,68.66 ; U2.24 -92.77,-29.77 ccw(c-92.77,-25) C7.2 ; U2.27 -141.71,29.29 ccw(c-141.71,40) -131,40 -131,68.66 ; U2.29 -131,68.66 ; C7.2@-83,-20 -78.57,-20 v1(-62.78,-4.22) -48.57,10 -44.8,10 R7.1
  Sign w10: v1(-62.78,-4.22) cw(c-62.78,18) -85,18 -85,55 cw(c-58,55) -58,82 v1(-52,82)
  Bottom Layer w10: v1(-52,82) cw(c-73.73,60.27) v1@-50.47,80.35
ENCODER_CLK: U4.13 U5.7 | length 239.3
  Top Layer w10: v1(285,-117) cw(c262.63,-139.37) 286.53,-118.64 cw(c262.63,-139.37) 294.09,-136.06 cw(c262.63,-139.37) 294.27,-139.37 U4.13
  Bottom Layer w10: U5.7 190.55,-63.98 cw(c190.55,-163.98) 261.27,-93.27 v1(285,-117)
ENCODER_CS: U4.12 U5.8 | length 138.2
  Top Layer w10: v1(207,-106) 207,-105.75 211.18,-101.57 U4.12
  Bottom Layer w10: U5.8 189.49,-89.57 190.57,-89.57 cw(c190.57,-106) v1(207,-106) v1@205.93,-106
ENCODER_MISO: U4.14 U5.5 | length 318.1
  Top Layer w10: U4.14@313.98,-160.59 v1(314,-64)
  Bottom Layer w10: U5.5 221.37,-12.8 cw(c221.37,-112.8) 292.08,-42.08 v1(314,-64)
ENCODER_MOSI: U4.15 U5.6 | length 296.6
  Top Layer w10: U4.15 333.76,-160.5 333.76,-117.24 v1(334,-117)
  Bottom Layer w10: U5.6 213.96,-38.39 cw(c213.96,-138.39) 284.68,-67.68 v1(334,-117)
FDCAN_RX: U1.4 U4.33 | length 1041.2
  Top Layer w10: U1.4 -102.58,-522.95 -102.58,-503.74 -101,-502.16 v1(-101,-500) ; v1(519,57) 520.09,55.91 U4.33
  Sign w10: v1(-101,-500) ccw(c-101,-497.59) -99.29,-499.29 -55,-455 ; -55,-455 ccw(c-79.14,-430.86) -45,-430.86 -45,-349 cw(c-1,-349) -1,-305 204.58,-305 ccw(c204.64,-159.29) 307.71,-262.29 489.71,-80.29 ccw(c419,-9.58) 490,-80 ccw(c419,-9.58) 519,-9.58 v1(519,57)
FDCAN_TX: U1.1 U4.34 | length 1060.7
  Top Layer w10: v1(-27,-499) -27,-523.86 U1.1 ; v1@519,83 ccw(c536.86,100.86) 536.86,75.6 U4.34
  Sign w10: v1(-27,-499) -27,-357 cw(c5,-357) 5,-325 207.53,-325 ccw(c207.57,-162.22) 322.71,-277.29 512.71,-87.29 ccw(c442,-16.58) 542,-16.58 542,60 ccw(c519,60) v1(519,83)
NetC3_1: C3.1 U2.3 | length 70.8
  Top Layer w10: C3.1 ccw(c-417.18,108.31) -417.18,48.97 U2.3
NetC4_1: C4.1 U2.1 | length 104.6
  Top Layer w10: C4.1 -444.07,141.9 cw(c-465.98,120) -435,120 ccw(c-410.86,120) -427.93,102.93 -420,95 ; -420,95 ccw(c-403.94,111.06) -403.94,88.35 U2.1
NetC4_2: C4.2 U2.2 | length 81.9
  Top Layer w10: C4.2 -458.77,108.77 -425,75 ; -425,75 ccw(c-409.69,90.31) -409.69,68.66 U2.2
NetC10_1: C10.1 U6.4 | length 55.1
  Top Layer w10: U6.4 151.52,-588.06 152.42,-588.97 C10.1
NetC10_2: C10.2 L1.1 U6.6
NetC11_1: C11.1 U4.5 Y1.3 | length 270.5
  Top Layer w10: C11.1@26.02,138.38 Y1.3 115.76,103.15 ccw(c130.11,117.5) 130.11,97.21 171.79,97.21 cw(c171.79,81) 188,81 188,57 ccw(c208.77,57) 208.77,36.23 U4.5
NetC13_1: C13.1 U4.7 | length 93.9
  Top Layer w10: C13.1@143.2,-10 cw(c159.77,-26.57) 159.77,-3.14 U4.7
NetC17_1: C17.1 U4.20 U7.2
NetC20_1: C20.1 U4.6 Y1.1 | length 268.7
  Top Layer w10: C20.1 cw(c50.58,-8.5) 50.58,16.54 108.31,16.54 ccw(c108.31,55.7) Y1.1 ccw(c186.63,55.7) 186.63,16.54 U4.6
NetC21_2: C21.2 U6.2 | length 75.1
  Top Layer w10: U6.2 100.34,-619.38 ccw(c125.93,-619.38) C21.2
NetC22_2: C22.2 L2.2 U4.21
NetD1_G: D1.G U2.6 | length 245.6
  Top Layer w10: v1(-485,123) -485,9 ccw(c-465.92,9) -465.92,-10.08 U2.6
  Bottom Layer w10: v1(-485,123) -485,119.33 ccw(c-469.06,119.33) D1.G@-469.06,103.39
NetD2_G: D2.G U2.8 | length 247.9
  Top Layer w10: v1@-469.98,-56.98 cw(c-451.78,-75.22) -451.78,-49.45 U2.8
  Sign w10: v1@-471.61,-58.53 ccw(c-501.38,-25.62) v1@-470,-57
  Bottom Layer w10: D2.G -586.18,-53.82 ccw(c-570,-53.82) -570,-70 -483,-70 ccw(c-483,-57) v1(-470,-57)
NetD2_S: D2.S R8.2 U2.9 | length 206.3
  Top Layer w10: R8.2 -550,-60 ccw(c-530,-60) -530,-80 -467.07,-80 ccw(c-467.07,-62.93) -455,-75 ; -455,-75 cw(c-440.86,-89.14) -440.86,-69.14 U2.9
  other v1: -561,-45 -535,-45 -509,-45 -548,-21 -522,-21 -497,-21
NetD3_G: D3.G U2.15 | length 261.8
  Top Layer w10: v1@-290,-175 ccw(c-298.04,-166.96) -287.05,-169.89 ccw(c-298.04,-166.96) -286.67,-166.96 U2.15
  Sign w10: v1(-442,-131) cw(c-435,-131) -435,-124 -320,-124 cw(c-320,-154) -290,-154 v1(-290,-175)
  Bottom Layer w10: v1(-442,-131) -442,-132 -441.78,-132.22 D3.G
NetD4_G: D4.G U2.13 | length 232.4
  Top Layer w10: v1(-327,-150) -326.12,-149.12 -326.12,-116.46 U2.13
  Sign w10: v1@-327,-150 ccw(c-288.37,-188.63) -343,-188.63 -343,-246.64 ccw(c-257.64,-246.64) v1@-318,-307
  Bottom Layer w10: D4.G -324.94,-290.25 ccw(c-301.25,-290.25) v1(-318,-307)
NetD4_S: D4.S R9.2 U2.12 | length 191.7
  Top Layer w10: U2.12 -345.73,-130.86 cw(c-400.94,-130.86) -361.93,-169.93 -375.98,-183.98 ccw(c-346.96,-213) -388,-213 -388,-230 ccw(c-366.7,-230) -366.64,-251.3 R9.2
  other v1: -301,-252 -321,-240 -301,-227 -321,-214 -301,-202
NetD5_G: D5.G U2.16 | length 23.8
  Top Layer w10: U2.16 -266.91,-116.46 -266.91,-139.31 v1(-266.32,-139.9)
NetD6_G: D6.G U2.18 | length 93.7
  Top Layer w10: v1(-241,-202) ccw(c-241,-188.62) -227.62,-188.62 U2.18
  Bottom Layer w10: D6.G@-241.06,-201.61 -241.06,-201.94 v1(-241,-202)
NetD6_S: D6.S R10.2 U2.19 | length 182.2
  Top Layer w10: R10.2 -206.3,-251.3 ccw(c-206.3,-235) -190,-235 -190,-194.13 ccw(c-224.12,-194.13) -199.99,-170.01 cw(c-180.83,-150.85) -207.93,-150.85 U2.19
  other v1: -271,-277 -251,-266 -271,-252 -251,-240 -270,-225
NetLED1_1: LED1.1 R5.2 | length 86.1
  Top Layer w10: R5.2 -264,330 ccw(c-264,360) LED1.1
NetLED2_1: LED2.1 R20.2 | length 81.6
  Top Layer w10: LED2.1 255.43,378 R20.2
NetR11_2: R11.2 U6.3 | length 100.7
  Top Layer w10: U6.3 125.93,-610.17 ccw(c139.83,-610.17) 130,-620 ; 130,-620 ccw(c138.57,-611.43) 138.57,-623.55 159.51,-623.55 cw(c159.51,-644.97) R11.2
NetR13_1: R13.1 U4.45 | length 63.2
  Top Layer w10: U4.45 353.33,232.77 cw(c359.03,232.77) R13.1
NetR16_1: R16.1 R18.2 R19.2 | length 181.5
  Top Layer w10: R19.2 cw(c22.26,-571.8) 0,-571.8 0,-511.03 cw(c22.26,-511.03) R18.2 R16.1
NetR18_1: R18.1 U6.1 | length 92.3
  Top Layer w10: R18.1 56.72,-536.97 cw(c56.72,-555) 74.75,-555 U6.1
PGND: C1.1 C2.1 C8.1 C9.1 C14.1 C15.1 C18.1 C19.1 C21.1 C25.1 C26.1 C27.1 C28.1 C29.1 C30.1 H1.3 H1.4 H1.7 H1.8 H2.3 H2.4 H2.8 R3.2 R4.2 R8.1 R9.1 R10.1 R17.2 R19.1 U2.10 U2.11 U2.20 U2.40 U2.41 U3.2 U6.5 | length 810.3
  Top Layer w10: R8.1 -550,-120 cw(c-530,-120) -530,-100 -462.07,-100 ccw(c-462.07,-82.93) -450,-95 ; R9.1 -427.3,-251.3 ccw(c-427.3,-229) -405,-229.09 -405,-208 cw(c-356.72,-208) -390.88,-173.88 -377.72,-160.72 ccw(c-407.44,-131) -365.41,-131.06 ccw(c-407.44,-131) -365.41,-131 U2.11 ; -450,-95 cw(c-435.09,-109.91) -435.09,-88.82 U2.10 ; C8.1 cw(c-208.2,-468.2) -195,-468.2 U3.2 ; U2.20 -188.25,-145.08 ccw(c-162.5,-145.08) -180.71,-163.29 cw(c-206.56,-189.14) -170,-189.14 -170,-235 ccw(c-153.7,-235) -153.7,-251.3 R10.1 ; R4.2@-40.8,-377 v1(-4,-377) ; R3.2@25,176.2 25.1,176.3 25.1,304.9 v1(25,305)
  other v1: -5,-695 20,-695 45,-695 70,-695 95,-695 120,-695 -5,-670 20,-670 45,-670 70,-670 95,-670 120,-670 -260,-645 -195,-645 -5,-645 45,-645 -260,-620 -195,-620 -260,-595 -195,-595 -260,-570 -195,-570 -170,-570 -260,-545 -260,-520 -260,-495 -260,-470 -260,-445 190,-410 210,-410 190,-365 210,-365 -44.39,-274.87 -25,-275 -5,-275 15,-275 35,-275 -45,-255 -25,-255 -5,-255 15,-255 35,-255 -520,-250 -500,-250 -44.39,-234.87 -25,-235 -5,-235 15,-235 35,-235 -660,-230 -640,-230 -620,-230 -520,-230 -500,-230 -45,-215 -25,-215 -5,-215 15,-215 35,-215 -660,-210 -640,-210 -620,-210 -600,-210 -580,-210 -560,-210 -540,-210 -520,-210 -500,-210 -480,-210 -44.39,-194.87 -25,-195 -5,-195 15,-195 35,-195 165,-195 185,-195 205,-195 225,-195 -660,-190 -640,-190 -620,-190 -600,-190 -580,-190 -560,-190 -540,-190 -520,-190 -500,-190 -480,-190 -25,-175 -5,-175 15,-175 35,-175 165,-175 185,-175 205,-175 225,-175 -660,-170 -640,-170 -620,-170 -600,-170 -500,-170 -480,-170 -5,-155 15,-155 35,-155 185,-155 205,-155 225,-155 -680,-150 -660,-150 -640,-150 -620,-150 -600,-150 -500,-150 -480,-150 -680,-130 -660,-130 -640,-130 -620,-130 -600,-130 -500,-130 -480,-130 -300,20 -280,20 -260,20 -240,20 -220,20 -200,20 -300,40 -280,40 -260,40 -240,40 -220,40 -200,40 -300,60 -280,60 -260,60 -240,60 -220,60 -200,60 -605,250 -585,250 -565,250 -605,270 -585,270 -565,270 -605,290 -585,290 -565,290 -605,310 -585,310 -565,310 -605,330 -585,330 -565,330 -605,350 -585,350 -565,350
SHA: D1.S D2.D pad.14@-595,165 U2.7 | length 161
  Top Layer w10: v1(-470,-31) -468.85,-29.85 -393.05,-29.85 U2.7
  Bottom Layer w10: v1(-470,-31) -470,49.94 cw(c-466.79,49.94) D1.S@-469.06,52.21
  other v1: -635,125 -610,125 -585,125 -635,150 -610,150 -585,150 -635,175 -610,175 -585,175 -635,200 -610,200 -585,200
SHB: D3.S D4.D pad.14@-396,-360 U2.14 | length 122.3
  Top Layer w10: v1(-320,-175) -317.64,-174.02 -315.8,-173.26 -314.39,-171.85 -314.12,-171.59 ccw(c-337.96,-150.84) -306.36,-150.84 U2.14
  Bottom Layer w10: -365,-157.13 -365,-165 ccw(c-357,-165) -357,-173 -355,-175 v1(-320,-175)
  other v1: -431,-400 -406,-400 -381,-400 -356,-400 -431,-375 -406,-375 -381,-375 -356,-375 -431,-350 -406,-350 -381,-350 -356,-350 -431,-325 -406,-325 -381,-325 -356,-325
SHC: D5.S D6.D pad.14@-227,-360 U2.17 | length 51.5
  Top Layer w8: v1(-248,-167) -246.62,-165.62 -246.62,-117.06 U2.17
  other v1: -266,-400 -241,-400 -216,-400 -191,-400 -266,-375 -241,-375 -216,-375 -191,-375 -266,-350 -241,-350 -216,-350 -191,-350 -266,-325 -241,-325 -216,-325 -191,-325
STATE_LED: R20.1 U4.46 | length 169.8
  Top Layer w10: R20.1 cw(c309,305.16) 333.64,305.16 U4.46
SW_Bit0: SW1.1 U4.44 | length 320.3
  Top Layer w10: v1(373,130) U4.44
  Sign w10: v1(150,269) 192.58,269 cw(c192.58,169) 263.29,239.71 v1(373,130)
SW_Bit1: SW1.2 U4.43 | length 322.6
  Top Layer w10: SW1.2@148,320 ccw(c150.41,322.41) v1(150.41,319) ; v1@385,221 cw(c366.4,202.4) 392.7,202.4 U4.43
  Sign w10: v1(150.41,319) 245.58,319 cw(c245.58,219) 316.29,289.71 v1(385,221)
SW_Bit2: SW1.3 U4.42 | length 379.2
  Top Layer w10: v1(150,354) SW1.3@150,362 ; v1(412,241) 412,174.4 U4.42
  Sign w10: v1(150,354) 253.65,354 cw(c253.72,244.67) 331.04,321.96 ; 331.07,321.93 v1(412,241)
SWCLK: CN1.3 R2.1 U4.38 | length 717.1
  Top Layer w10: CN1.3 25.2,523.9 R2.1 25,446.18 25,429 ccw(c50,429) 50,404 312.58,404 cw(c312.58,304) 383.29,374.71 461.83,296.17 cw(c391.12,225.46) 491.12,225.46 U4.38
SWDIO: CN1.4 R1.1 U4.37 | length 685.8
  Top Layer w10: CN1.4 73.82,446.82 cw(c73,446.82) R1.1 73,436 ccw(c87,436) 87,422 319.58,422 cw(c319.58,322) 390.29,392.71 481.52,301.48 cw(c410.81,230.77) 510.81,230.77 U4.37
VBUS: C1.2 C2.2 C3.2 C14.2 C15.2 C25.2 C26.2 C27.2 C28.2 C29.2 C30.2 D1.D D3.D D5.D H1.1 H1.2 H2.1 H2.2 R11.1 R15.2 U2.4 U2.5 U6.7 | length 331.5
  Top Layer w10: v1(175,-675) ccw(c175,-616.83) 188.26,-673.47 ccw(c175,-616.83) 204.82,-666.78 ccw(c175,-616.83) 216.13,-657.96 R11.1
  Bottom Layer w10: H1.1 147.16,-607.8 ccw(c242.2,-607.8) v1(175,-675)
  other v1: 89,-417 89,-362
  other v2: -415,20
pads on no net: U2.28 U3.4 U4.2 U4.3 U4.4 U4.22 U4.26 U4.39 U4.40 U4.41 U5.1 U5.2 U5.3 U5.10 U5.13 U5.14 U5.15 U5.16 U6.8

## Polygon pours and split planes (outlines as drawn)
SHA on Bottom Layer "SHA_L04_P002" (solid, remove dead copper, pour order 2): -640,230 -660,210 -660,120 -600,60 -600,5 -440,5 -440,85 -495,85 -495,125 -560,125 -560,230
PGND on Bottom Layer "Bottom Layer-PGND" (solid, remove dead copper, pour order 46): -303.2,-643.93 -286.34,-651.28 -236.34,-670.89 -191.34,-685.89 -135.53,-698.27 -85.97,-705.14 -40.59,-708.72 -2.97,-710.81 51.07,-709.02 91.97,-704.54 130.49,-698.27 168.41,-690.15 213.66,-675.89 227.97,-669.86 238.66,-662.41 238.66,-210 385,-210 385,-145 238.66,-145 -173.84,-145 -173.84,370 46.16,370 46.16,703.41 23.89,705.45 -58.35,703.3 -140.59,691.8 -214.93,672.77 -297.17,642.6 -358.94,609.92 -429.69,561.08 -484.28,516.55 -530.6,469.51 -576.57,410.61 -608.53,363.56 -631.52,318.67 -654.86,267.68 -675.69,209.5 -688.26,162.81 -690.41,142.34 -689.7,126.18 -683.93,109.9 -674.57,100.79 -662.26,92.66 -650.19,86.26 -629.75,73.94 -614.73,57.94 -606.6,40.2 -603.65,20.01 -600.45,-1.42 -602.17,-22.35 -608.57,-45.99 -619.9,-60.27 -635.66,-73.82 -651.42,-82.68 -662.26,-89.58 -674.08,-98.69 -683.93,-108.05 -690.83,-123.32 -693.29,-140.06 -693.54,-156.32 -688.36,-180.21 -678.51,-216.66 -670.88,-233.16 -661.52,-244.73 -650.68,-248.42 -640.34,-248.18 -628.27,-244.24 -614.73,-238.33 -594.78,-230.69 -578.53,-227.24 -564.74,-228.48 -547.25,-234.14 -537.89,-242.51 -524.84,-262.22 -513.02,-284.63 -481,-346.19 -477.56,-363.93 -481.99,-379.93 -489.62,-394.22 -505.63,-405.05 -531.24,-424.26 -537.15,-434.36 -541.09,-444.46 -539.62,-460.46 -532.23,-474.99 -515.24,-491.99 -469.68,-535.33 -421.16,-573.26 -367.47,-609.46
VBUS on Bottom Layer "Bottom Layer-VBUS" (solid, remove dead copper, pour order 22): -455,-110 -157,-110 -157,-4 -320,-4 -320,110 -365,155 -365,176.34 -341.34,200 -170,200 -130,160 410,160 450,120 450,-160 385,-225 60,-225 60,-470 175,-470 175,-350 440,-350 560,-230 560,180 470,270 25,270 -65,360 -65,475 -435,475 -435,-5 -455,-5
DGND on Bottom Layer "DGND_L04_P047" (solid, remove dead copper, pour order 47): -170,-140 -170,273.61 62.57,273.61 62.57,704.03 99.63,700.63 183.31,683.75 259.8,658.97 343.48,619.11 398.06,586.42 462.71,535.79 520.53,479.41 565.06,422.66 589.48,387.47 611.39,353.35 637.6,304.51 655.92,266.08 672.8,222.27 684.29,181.33 687.52,161.94 687.52,138.59 683.57,118.48 673.87,105.55 656.28,93.34 632.57,77.9 613.9,58.87 600.25,38.76 593.43,12.9 593.79,-8.65 599.89,-31.27 609.59,-49.59 618.93,-63.95 631.5,-78.32 647.3,-89.45 665.97,-98.07 678.54,-112.8 686.08,-132.55 686.96,-154.97 676.95,-199.29 658.36,-252.67 629.29,-318.44 592.6,-380.39 544.94,-448.54 468.21,-525.74 401.02,-579.6 345.73,-620.58 284.73,-647.27 250.07,-660.59 250.07,-140
NetD6_S on Bottom Layer "NETD6_S_L04_P009" (solid, remove dead copper, pour order 9): -280,-220 -280,-290 -225,-290 -225,-220
NetD4_S on Bottom Layer "NETD4_S_L04_P008" (solid, remove dead copper, pour order 8): -345,-190 -345,-265 -290,-265 -290,-190
SHC on Bottom Layer "SHC_L04_P007" (solid, remove dead copper, pour order 7): -260,-120 -260,-185 -215,-185 -215,-300 -270,-300 -290,-320 -290,-400 -270,-420 -185,-420 -175,-410 -175,-360 -175,-355 -110,-290 -110,-170 -160,-120
SHB on Bottom Layer "SHB_L04_P006" (solid, remove dead copper, pour order 6): -425,-120 -425,-190 -460,-190 -460,-400 -440,-420 -355,-420 -335,-400 -335,-310 -355,-290 -355,-120
NetD2_S on Bottom Layer "NETD2_S_L04_P003" (solid, remove dead copper, pour order 3): -570,-5 -570,-55 -486,-55 -486,-5
PGND on Top Layer "GND-PGND" (solid, remove dead copper, pour order 50): -357.6,610.82 -357.6,580 -357.6,-140 240,-140 240,-661.51 229.3,-668.97 215,-675 169.75,-689.26 131.83,-697.38 93.31,-703.65 52.41,-708.13 -1.63,-709.92 -39.25,-707.83 -84.63,-704.25 -134.19,-697.38 -190,-685 -235,-670 -285,-650.39 -301.86,-643.04 -366.13,-608.57 -419.82,-572.36 -468.34,-534.44 -513.9,-491.09 -530.89,-474.1 -538.28,-459.57 -539.76,-443.56 -535.82,-433.47 -529.91,-423.37 -504.29,-404.16 -488.28,-393.32 -480.65,-379.04 -476.22,-363.03 -479.67,-345.3 -511.68,-283.73 -523.5,-261.32 -536.55,-241.62 -545.91,-233.25 -563.4,-227.58 -577.19,-226.35 -593.44,-229.8 -613.39,-237.44 -626.94,-243.35 -639,-247.29 -649.35,-247.53 -660.18,-243.84 -669.54,-232.26 -677.18,-215.76 -687.03,-179.31 -692.2,-155.43 -691.95,-139.17 -689.49,-122.43 -682.59,-107.16 -672.74,-97.8 -660.92,-88.69 -650.09,-81.79 -634.32,-72.93 -618.56,-59.38 -607.23,-45.1 -600.83,-21.46 -599.11,-0.52 -602.31,20.9 -605.26,41.1 -613.39,58.83 -628.41,74.84 -648.85,87.15 -660.92,93.55 -673.24,101.68 -682.59,110.79 -688.36,127.07 -689.08,143.23 -686.92,163.7 -674.35,210.39 -653.52,268.57 -630.18,319.56 -607.2,364.45 -575.23,411.5 -529.27,470.4 -482.94,517.44 -428.35,561.97
DGND on Top Layer "Top Layer-DGND 1" (solid, remove dead copper, pour order 51): -340,-125 250,-125 250,-661.7 284.67,-648.38 345.67,-621.69 400.95,-580.7 468.15,-526.85 544.87,-449.65 592.53,-381.5 629.23,-319.54 658.3,-253.78 676.88,-200.4 686.89,-156.08 686.02,-133.66 678.48,-113.9 665.91,-99.18 647.23,-90.56 631.43,-79.43 618.86,-65.06 609.52,-50.7 599.83,-32.38 593.72,-9.76 593.36,11.79 600.19,37.65 613.83,57.76 632.51,76.79 656.21,92.24 673.81,104.45 683.5,117.38 687.45,137.49 687.45,160.83 684.22,180.22 672.73,221.16 655.85,264.98 637.54,303.4 611.32,352.24 589.41,386.36 564.99,421.56 520.46,478.3 462.64,534.68 398,585.32 343.41,618 259.74,657.86 183.24,682.64 99.56,699.52 80,701.32 25.23,706.34 -57.01,704.19 -139.25,692.7 -213.59,673.66 -295.83,643.5 -340,620.13
PGND on Top Layer "PGND_L01_P043" (solid, remove dead copper, pour order 43): -685,-115 -430,-115 -430,-285 -510,-285 -531.54,-250.97 -538.77,-241.33 -548.94,-233.84 -564.2,-227.95 -579.45,-227.68 -600.87,-232.23 -615.59,-239.19 -633.79,-245.35 -649.32,-247.22 -660.03,-243.21 -669.39,-232.77 -675.28,-217.24 -684.92,-178.7 -690.81,-155.14 -691.88,-135.33 -685.72,-116.06
PGND on Top Layer "PGND_L01_P036" (solid, remove dead copper, pour order 36): -270,-435 -270,-655 -235,-670 -190,-685 -134.19,-697.38 -84.63,-704.25 -39.25,-707.83 -1.63,-709.92 52.41,-708.13 93.31,-703.65 131.83,-697.38 169.75,-689.26 215,-675 229.3,-668.97 240,-661.51 240,-140 -145,-140 -145,-435
3V3 on Top Layer "3V3_L01_P035" (solid, remove dead copper, pour order 35): -175,-585 -175,-675 -125,-675 -95,-645 -95,-620 -120,-620 -120,-585
DGND on Top Layer "DGND_L01_P034" (solid, remove dead copper, pour order 34): 485,-130 500,-130 500,-205 525,-230 525,-285 520,-290 490,-290 475,-275 475,-205 485,-195
3V3 on Top Layer "3V3_L01_P033" (solid, remove dead copper, pour order 33): 505,-130 505,-200 535,-230 535,-285 515,-305 515,-375 430,-375 430,-495 470,-495 470,-455 510,-455 535,-430 535,-330 565,-300 565,-220 520,-175 520,-130
NetC22_2 on Top Layer "NETC22_2_L01_P032" (solid, remove dead copper, pour order 32): 445,-130 445,-245 430,-260 430,-365 505,-365 505,-300 485,-300 465,-280 465,-205 460,-200 460,-130
DGND on Top Layer "Top Layer-DGND" (solid, remove dead copper, pour order 31): 340,-290 350,-300 350,-485 385,-485 385,-450 380,-445 380,-250 420,-210 420,-130 405,-130 405,-200 340,-265
NetC17_1 on Top Layer "NETC17_1_L01_P029" (solid, remove dead copper, pour order 29): 425,-130 440,-130 440,-235 420,-255 420,-440 385,-440 385,-255 425,-215
5V on Top Layer "5V_L01_P027" (solid, remove dead copper, pour order 27): 170,-430 170,-485 340,-485 340,-310 230,-310 230,-430
PGND on Top Layer "PGND_L01_P026" (solid, remove dead copper, pour order 26): 120,-360 120,-455 145,-455 145,-520 160,-520 160,-420 220,-420 220,-310 170,-310 170,-360
NetC10_2 on Top Layer "NETC10_2_L01_P025" (solid, remove dead copper, pour order 25): 115,-465 115,-550 170,-550 170,-570 230,-570 230,-605 275,-605 275,-500 170,-500 170,-525 135,-525 135,-465
VBUS on Top Layer "VBUS_L01_P013" (solid, remove dead copper, pour order 13): 65,-325 65,-435 90,-460 90,-525 110,-525 110,-325
NetD6_S on Top Layer "NETD6_S_L01_P011" (solid, remove dead copper, pour order 11): -280,-215 -280,-285 -210,-285 -210,-215
NetD4_S on Top Layer "NETD4_S_L01_P010" (solid, remove dead copper, pour order 10): -365,-285 -290,-285 -290,-191.79 -365,-191.79
NetD2_S on Top Layer "NETD2_S_L01_P004" (solid, remove dead copper, pour order 4): -585,5 -585,-55 -485,-55 -485,-5 -485,5
VBUS on Top Layer "VBUS_L01_P001" (solid, remove dead copper, pour order 1): -470,40 -470,5 -380,5 -380,35 -445,35 -450,40
PGND on GND "GND-PGND" (solid, remove dead copper, pour order 42): -301.86,-643.04 -285,-650.39 -235,-670 -190,-685 -134.19,-697.38 -84.63,-704.25 -39.25,-707.83 -1.63,-709.92 52.41,-708.13 93.31,-703.65 131.83,-697.38 169.75,-689.26 215,-675 229.3,-668.97 240,-661.51 240,-140 -172.5,-140 -172.5,280 cw(c-165,280) -165,287.5 47.5,287.5 47.5,704.3 25.23,706.34 -57.01,704.19 -139.25,692.7 -213.59,673.66 -295.83,643.5 -357.6,610.82 -428.35,561.97 -482.94,517.44 -529.27,470.4 -575.23,411.5 -607.2,364.45 -630.18,319.56 -653.52,268.57 -674.35,210.39 -686.92,163.7 -689.08,143.23 -688.36,127.07 -682.59,110.79 -673.24,101.68 -660.92,93.55 -648.85,87.15 -628.41,74.84 -613.39,58.83 -605.26,41.1 -602.31,20.9 -599.11,-0.52 -600.83,-21.46 -607.23,-45.1 -618.56,-59.38 -634.32,-72.93 -650.09,-81.79 -660.92,-88.69 -672.74,-97.8 -682.59,-107.16 -689.49,-122.43 -691.95,-139.17 -692.2,-155.43 -687.03,-179.31 -677.18,-215.76 -669.54,-232.26 -660.18,-243.84 -649.35,-247.53 -639,-247.29 -626.94,-243.35 -613.39,-237.44 -593.44,-229.8 -577.19,-226.35 -563.4,-227.58 -545.91,-233.25 -536.55,-241.62 -523.5,-261.32 -511.68,-283.73 -479.67,-345.3 -476.22,-363.03 -480.65,-379.04 -488.28,-393.32 -504.29,-404.16 -529.91,-423.37 -535.82,-433.47 -539.76,-443.56 -538.28,-459.57 -530.89,-474.1 -513.9,-491.09 -468.34,-534.44 -419.82,-572.36 -366.13,-608.57
DGND on GND "DGND_L02_P041" (solid, remove dead copper, pour order 41): -157.5,-125 -157.5,272.5 62.5,272.5 62.5,702.92 99.56,699.52 183.24,682.64 259.74,657.86 343.41,618 398,585.32 462.64,534.68 520.46,478.3 564.99,421.56 589.41,386.36 611.32,352.24 637.54,303.4 655.85,264.98 672.73,221.16 684.22,180.22 687.45,160.83 687.45,137.49 683.5,117.38 673.81,104.45 656.21,92.24 632.51,76.79 613.83,57.76 600.19,37.65 593.36,11.79 593.72,-9.76 599.83,-32.38 609.52,-50.7 618.86,-65.06 631.43,-79.43 647.23,-90.56 665.91,-99.18 678.48,-113.9 686.02,-133.66 686.89,-156.08 676.88,-200.4 658.3,-253.78 629.23,-319.54 592.53,-381.5 544.87,-449.65 468.15,-526.85 400.95,-580.7 345.67,-621.69 284.67,-648.38 250,-661.7 250,-125
PGND on Sign "Sign-PGND" (solid, remove dead copper, pour order 44): -127.5,-615 -127.5,-310 cw(c-120,-310) -120,-302.5 235,-302.5 235,-140 -137.5,-140 -137.5,167.35 -392.55,162.35 -390.99,394.74 -589.18,394.74 -615.18,351.69 -639,303.4 -657.17,258.95 -674.35,210.39 -686.92,163.7 -689.08,143.23 -688.36,127.07 -682.59,110.79 -673.24,101.68 -660.92,93.55 -648.85,87.15 -628.41,74.84 -613.39,58.83 -605.26,41.1 -602.31,20.9 -599.11,-0.52 -600.83,-21.46 -607.23,-45.1 -618.56,-59.38 -634.32,-72.93 -650.09,-81.79 -660.92,-88.69 -672.74,-97.8 -682.59,-107.16 -689.49,-122.43 -691.95,-139.17 -692.2,-155.43 -687.03,-179.31 -677.18,-215.76 -669.54,-232.26 -660.18,-243.84 -649.35,-247.53 -639,-247.29 -626.94,-243.35 -613.39,-237.44 -593.44,-229.8 -577.19,-226.35 -563.4,-227.58 -545.91,-233.25 -536.55,-241.62 -523.5,-261.32 -511.68,-283.73 -479.67,-345.3 -476.22,-363.03 -480.65,-379.04 -488.28,-393.32 -504.29,-404.16 -529.91,-423.37 -535.82,-433.47 -539.76,-443.56 -538.28,-459.57 -530.89,-474.1 -513.9,-491.09 -468.34,-534.44 -419.82,-572.36 -366.13,-608.57 -301.86,-643.04 -240,-670 -165.9,-693.71 -71.83,-708.82 22.08,-711.28 103.57,-701.27 194.12,-683.16 235,-667.46 235,-622.5 -120,-622.5 cw(c-120,-615)
DGND on Sign "Sign-DGND" (solid, remove dead copper, pour order 48): 247.5,-607.5 247.5,-662.66 284.67,-648.38 345.67,-621.69 400.95,-580.7 468.15,-526.85 544.87,-449.65 592.53,-381.5 629.23,-319.54 658.3,-253.78 676.88,-200.4 686.89,-156.08 686.02,-133.66 678.48,-113.9 665.91,-99.18 647.23,-90.56 631.43,-79.43 618.86,-65.06 609.52,-50.7 599.83,-32.38 593.72,-9.76 593.36,11.79 600.19,37.65 613.83,57.76 632.51,76.79 656.21,92.24 673.81,104.45 683.5,117.38 687.45,137.49 687.45,160.83 684.22,180.22 672.73,221.16 655.85,264.98 637.54,303.4 611.32,352.24 589.41,386.36 564.99,421.56 520.46,478.3 462.64,534.68 398,585.32 343.41,618 259.74,657.86 183.24,682.64 99.56,699.52 25.23,706.34 -57.01,704.19 -139.25,692.7 -213.59,673.66 -295.83,643.5 -357.6,610.82 -428.35,561.97 -482.94,517.44 -529.27,470.4 -575.23,411.5 -378.98,410.86 -380.14,177.6 -122.5,182.65 -122.5,-130 247.5,-130 247.5,-317.5 -112.5,-317.5 -112.5,-607.5

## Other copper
Top Layer:
  pour cut-out: 520,-130 540,-110 540,-70 475,-70 405,0 265,0 265,-105 285,-125 285,-250 355,-250 405,-200 405,-130
  pour cut-out: -390,100 -390,-115 -160,-115 -160,100

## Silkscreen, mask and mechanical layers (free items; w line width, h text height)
Top Overlay:
  drawing of 32 lines, arcs and shapes, not listed
  text "A" at -615,240 h60
  text "B" at -445,-495 h60
  text "C" at -295,-495 h60
Bottom Overlay:
  drawing of 4 lines, arcs and shapes, not listed
  text "ZQ Motor" at 548,236.28 h60
Mechanical 1:
  circle w10: c-351.07,-557.07 r44.12
  circle w10: c351.07,557.07 r44.12
  lines w10: -703.91,-162.57 ccw(c0,0) -682.28,-237.53 ccw(c-645.1,-224.58) -630.03,-260.96 -589.18,-244.04 cw(c-574.11,-280.41) -540.02,-260.73 -495.81,-337.31 cw(c-529.9,-356.99) -505.93,-388.23 -541.01,-415.14 ccw(c-517.04,-446.38) -546.84,-472.1 ccw(c0,0) 703.91,-162.57 ccw(c627.19,-144.85) 658.08,-72.43 cw(c688.98,0) 657.17,72.03 ccw(c625.35,144.06) 702.08,161.73 ccw(c0,0) -702.08,161.73 ccw(c-625.35,144.06) -657.17,72.03 cw(c-688.98,0) -658.08,-72.43 ccw(c-627.19,-144.85) -703.91,-162.57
